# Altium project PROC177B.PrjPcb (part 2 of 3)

## Sheet PROC177B_Temp_Current_sensors_EPROM.SchDoc: TEMP_CURRENT_SENSORS_EEPROM
size 431 x 279 mm; Date: Not shown in title block; ApprovedBy: Not shown in title block; CheckedBy: Not shown in title block; Author: Not shown in title block; CompanyName: Not shown in title block; DrawnBy: Mistral; Engineer: Not shown in title block; Organization: Not shown in title block; Address1: Not shown in title block; Address2: Not shown in title block; Address3: Not shown in title block; Address4: Not shown in title block; DocumentNumber: 8; Revision: Use project parameter SCH_Rev; SheetNumber: 8; SheetTotal: 17; PageSetup: Record=PageOptions¦CenterHorizontal=True¦CenterVertical=True¦PrintScale=1.00¦XCorrection=1.00¦YCorrection=1.00¦PrintKind=0¦BorderSize=5000000¦LeftOffset=0¦BottomOffset=0¦Orientation=2¦PaperLength=1000¦PaperWidth=1000¦Scale=100¦PaperSource=15¦PrintQuality=600¦MediaType=1¦DitherType=10¦PaperKind=Letter¦PrintScaleMode=1
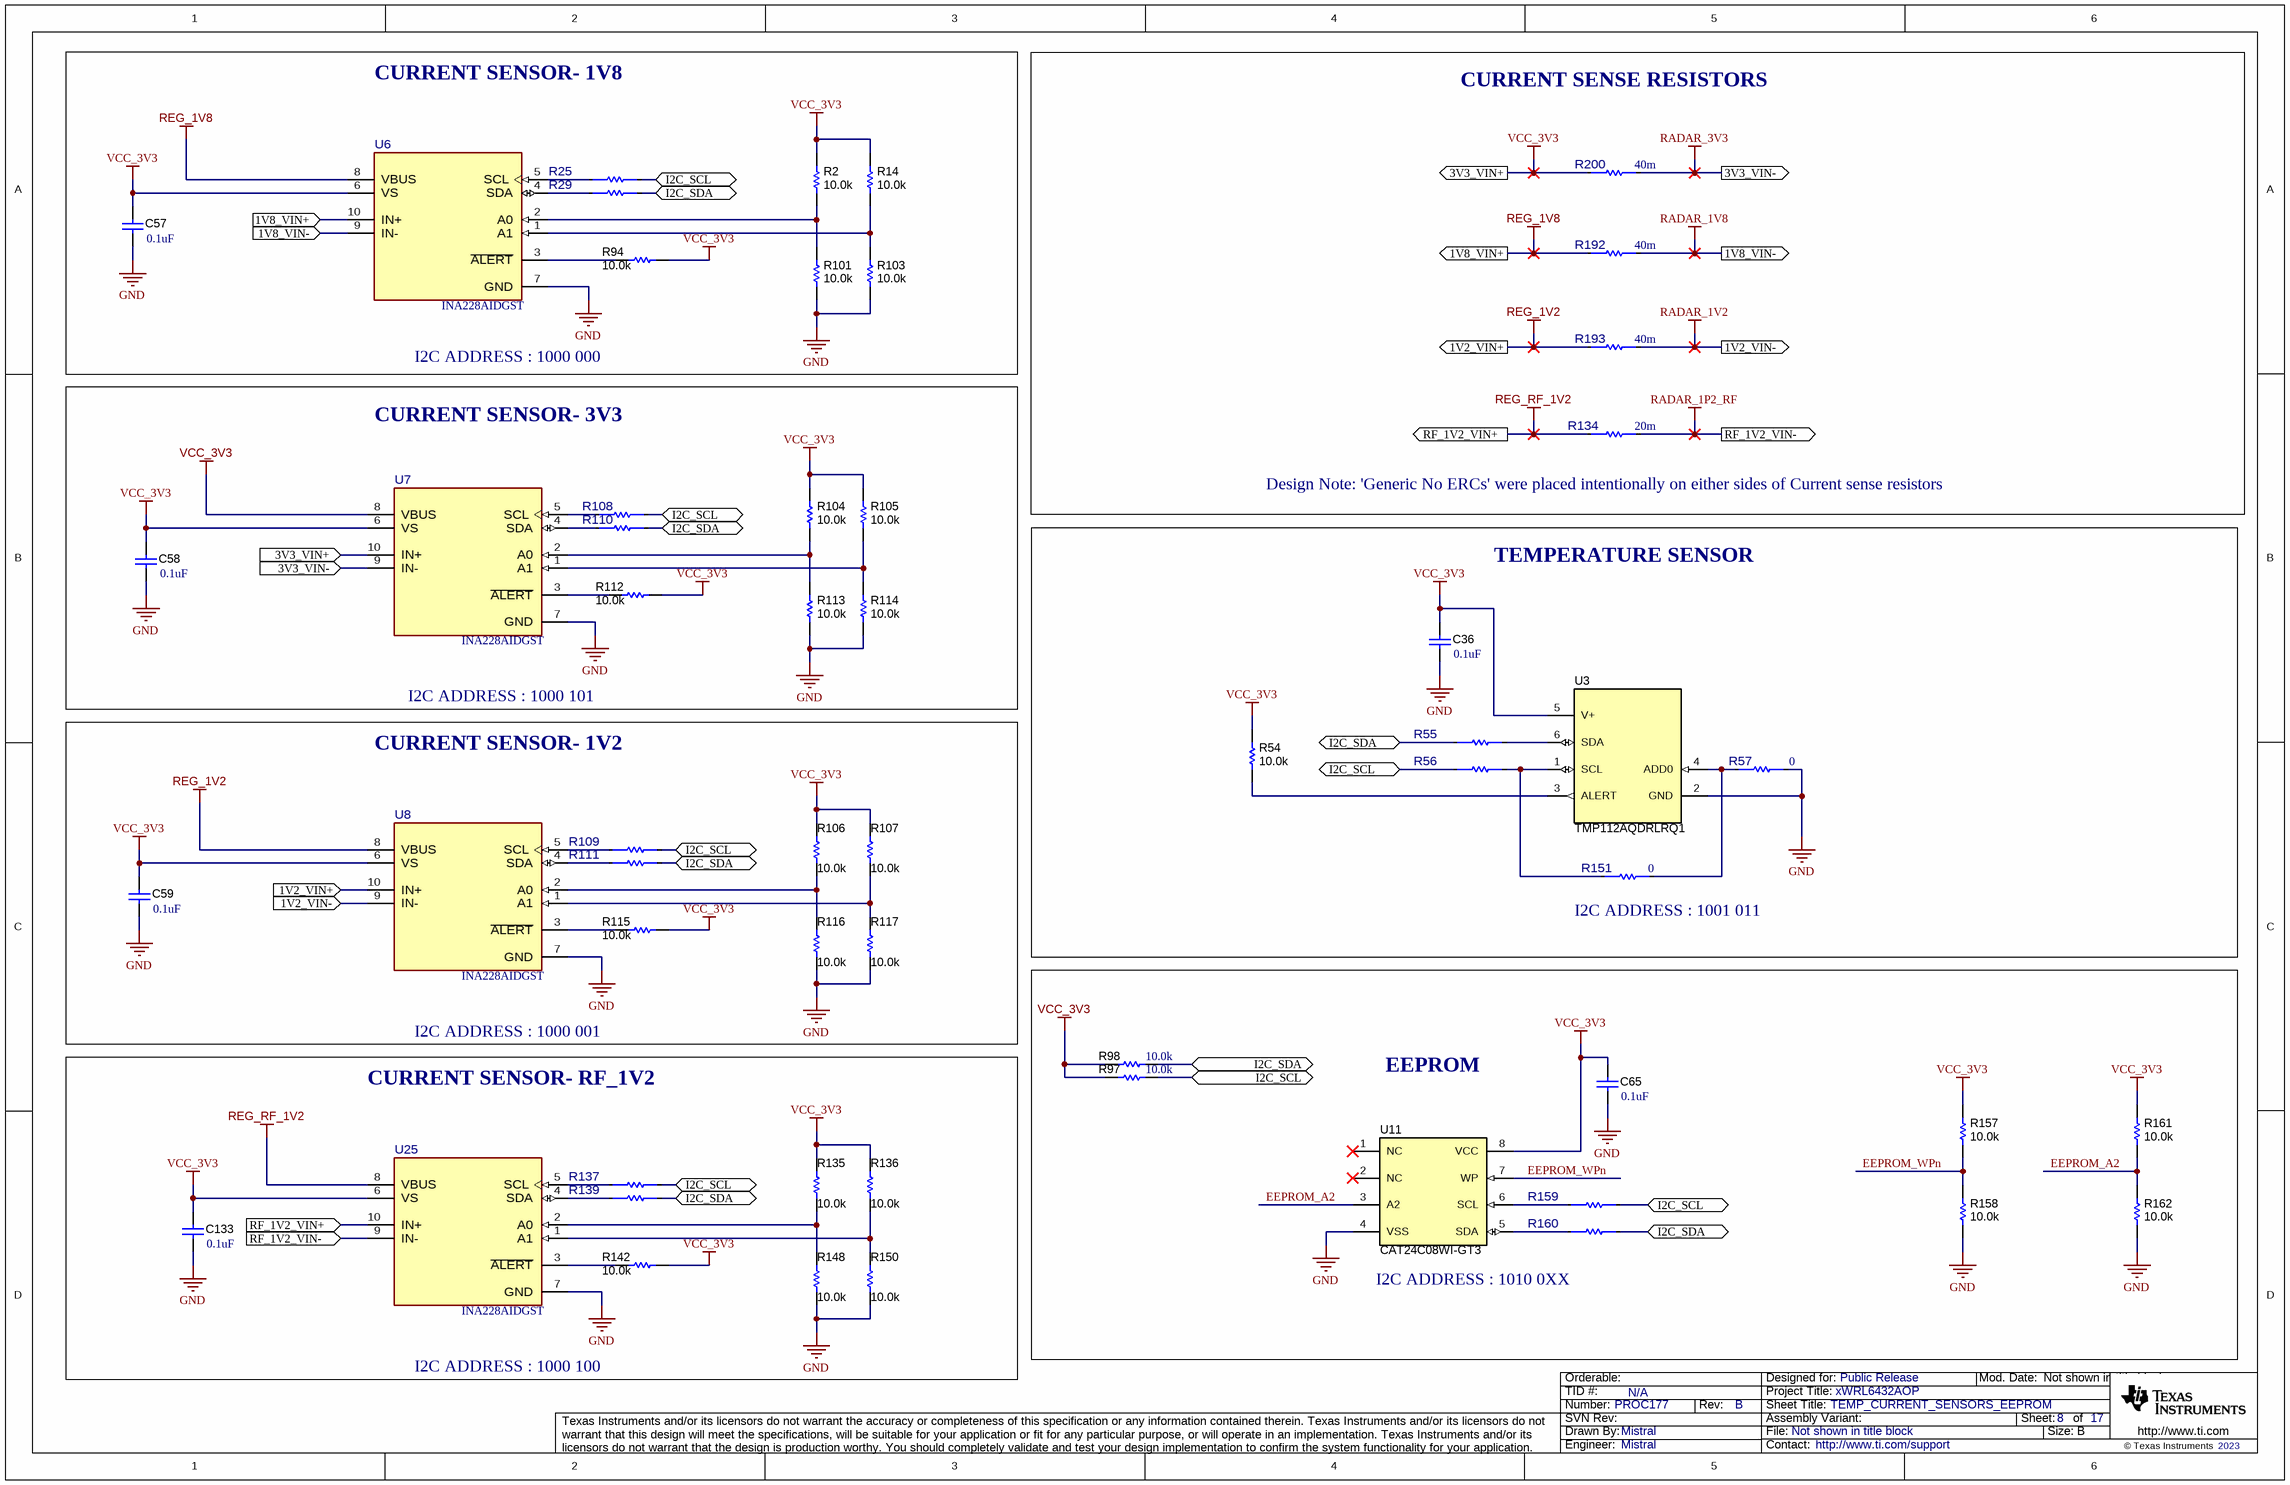
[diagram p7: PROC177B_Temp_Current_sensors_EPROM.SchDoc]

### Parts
C36  ValueDisplayed: 0.1uF  [0402]  (hidden comment: GCM155R71H104KE02D)
C57  ValueDisplayed: 0.1uF  [0402]  (hidden comment: GCM155R71H104KE02D)
C58  ValueDisplayed: 0.1uF  [0402]  (hidden comment: GCM155R71H104KE02D)
C59  ValueDisplayed: 0.1uF  [0402]  (hidden comment: GCM155R71H104KE02D)
C65  ValueDisplayed: 0.1uF  [0402]  (hidden comment: GCM155R71H104KE02D)
C133  ValueDisplayed: 0.1uF  [0402]  (hidden comment: GCM155R71H104KE02D)
R2  ValueDisplayed: 10.0k  [0402L]  (hidden comment: CRCW040210K0FKED)
R14  ValueDisplayed: 10.0k  [0402L]  (hidden comment: CRCW040210K0FKED)
R25  ERJ-2GE0R00X  [FP-ERJ-2GE0R00X_0402-MFG]  (value not drawn)
R29  ERJ-2GE0R00X  [FP-ERJ-2GE0R00X_0402-MFG]  (value not drawn)
R54  ValueDisplayed: 10.0k  [0402L]  (hidden comment: CRCW040210K0FKED)
R55  ERJ-2GE0R00X  [FP-ERJ-2GE0R00X_0402-MFG]  (value not drawn)
R56  ERJ-2GE0R00X  [FP-ERJ-2GE0R00X_0402-MFG]  (value not drawn)
R57  Res_ohm: 0  [FP-ERJ-2GE0R00X_0402-MFG]  (hidden comment: ERJ-2GE0R00X)
R94  ValueDisplayed: 10.0k  [0402L]  (hidden comment: CRCW040210K0FKED)
R97  ValueDisplayed: 10.0k  [0402L]  (hidden comment: CRCW040210K0FKED)
R98  ValueDisplayed: 10.0k  [0402L]  (hidden comment: CRCW040210K0FKED)
R101  ValueDisplayed: 10.0k  [0402L]  (hidden comment: CRCW040210K0FKED)
R103  ValueDisplayed: 10.0k  [0402L]  (hidden comment: CRCW040210K0FKED)
R104  ValueDisplayed: 10.0k  [0402L]  (hidden comment: CRCW040210K0FKED)
R105  ValueDisplayed: 10.0k  [0402L]  (hidden comment: CRCW040210K0FKED)
R106  ValueDisplayed: 10.0k  [0402L]  (hidden comment: CRCW040210K0FKED)
R107  ValueDisplayed: 10.0k  [0402L]  (hidden comment: CRCW040210K0FKED)
R108  ERJ-2GE0R00X  [FP-ERJ-2GE0R00X_0402-MFG]  (value not drawn)
R109  ERJ-2GE0R00X  [FP-ERJ-2GE0R00X_0402-MFG]  (value not drawn)
R110  ERJ-2GE0R00X  [FP-ERJ-2GE0R00X_0402-MFG]  (value not drawn)
R111  ERJ-2GE0R00X  [FP-ERJ-2GE0R00X_0402-MFG]  (value not drawn)
R112  ValueDisplayed: 10.0k  [0402L]  (hidden comment: CRCW040210K0FKED)
R113  ValueDisplayed: 10.0k  [0402L]  (hidden comment: CRCW040210K0FKED)
R114  ValueDisplayed: 10.0k  [0402L]  (hidden comment: CRCW040210K0FKED)
R115  ValueDisplayed: 10.0k  [0402L]  (hidden comment: CRCW040210K0FKED)
R116  ValueDisplayed: 10.0k  [0402L]  (hidden comment: CRCW040210K0FKED)
R117  ValueDisplayed: 10.0k  [0402L]  (hidden comment: CRCW040210K0FKED)
R134  value 20m  [FP-WSL1206R0200FEB_1206-MFG]  (hidden comment: WSL1206R0200FEB)
R135  ValueDisplayed: 10.0k  [0402L]  (hidden comment: CRCW040210K0FKED)
R136  ValueDisplayed: 10.0k  [0402L]  (hidden comment: CRCW040210K0FKED)
R137  ERJ-2GE0R00X  [FP-ERJ-2GE0R00X_0402-MFG]  (value not drawn)
R139  ERJ-2GE0R00X  [FP-ERJ-2GE0R00X_0402-MFG]  (value not drawn)
R142  ValueDisplayed: 10.0k  [0402L]  (hidden comment: CRCW040210K0FKED)
R148  ValueDisplayed: 10.0k  [0402L]  (hidden comment: CRCW040210K0FKED)
R150  ValueDisplayed: 10.0k  [0402L]  (hidden comment: CRCW040210K0FKED)
R151  Res_ohm: 0  [FP-ERJ-2GE0R00X_0402-MFG]  (hidden comment: ERJ-2GE0R00X)
R157  ValueDisplayed: 10.0k  [0402L]  (hidden comment: CRCW040210K0FKED)
R158  ValueDisplayed: 10.0k  [0402L]  (hidden comment: CRCW040210K0FKED)
R159  ERJ-2GE0R00X  [FP-ERJ-2GE0R00X_0402-MFG]  (value not drawn)
R160  ERJ-2GE0R00X  [FP-ERJ-2GE0R00X_0402-MFG]  (value not drawn)
R161  ValueDisplayed: 10.0k  [0402L]  (hidden comment: CRCW040210K0FKED)
R162  ValueDisplayed: 10.0k  [0402L]  (hidden comment: CRCW040210K0FKED)
R192  value 40m  [FP-WSL1206R0400FEB_1206-MFG]  (hidden comment: WSL1206R0400FEB)
R193  value 40m  [FP-WSL1206R0400FEB_1206-MFG]  (hidden comment: WSL1206R0400FEB)
R200  value 40m  [FP-WSL1206R0400FEB_1206-MFG]  (hidden comment: WSL1206R0400FEB)
U3  TMP112AQDRLRQ1  [DRL0006A]
U6  INA228AIDGST  [DGS0010A-MFG]
U7  INA228AIDGST  [DGS0010A-MFG]
U8  INA228AIDGST  [DGS0010A-MFG]
U11  CAT24C08WI-GT3  [SOIC-8]
U25  INA228AIDGST  [DGS0010A-MFG]

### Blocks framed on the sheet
CURRENT SENSOR- 1V8: C57 R2 R14 R25 R29 R94 R101 R103 U6
CURRENT SENSE RESISTORS: R134 R192 R193 R200
CURRENT SENSOR- 3V3: C58 R104 R105 R108 R110 R112-R114 U7
TEMPERATURE SENSOR: C36 R54-R57 R151 U3
CURRENT SENSOR- 1V2: C59 R106 R107 R109 R111 R115-R117 U8
EEPROM: C65 R97 R98 R157-R162 U11
CURRENT SENSOR- RF_1V2: C133 R135-R137 R139 R142 R148 R150 U25

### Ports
1V2_VIN+ (in), 1V2_VIN+ (out), 1V2_VIN- (in), 1V2_VIN- (out), 1V8_VIN+ (in), 1V8_VIN+ (out), 1V8_VIN- (in), 1V8_VIN- (out), 3V3_VIN+ (in), 3V3_VIN+ (out), 3V3_VIN- (in), 3V3_VIN- (out), I2C_SCL (bidir), I2C_SDA (bidir), RF_1V2_VIN+ (in), RF_1V2_VIN+ (out), RF_1V2_VIN- (in), RF_1V2_VIN- (out)

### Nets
GND: C36.2 C57.2 C58.2 C59.2 C65.2 C133.2 R57.2 R101.1 R103.1 R113.1 R114.1 R116.1 R117.1 R148.1 R150.1 R158.1 R162.1 U3.2(GND) U6.7(GND) U7.7(GND) U8.7(GND) U11.4(VSS) U25.7(GND)
RADAR_1P2_RF: R134.2 U25.9(IN-) ; port RF_1V2_VIN-
RADAR_1V2: R193.2 U8.9(IN-) ; port 1V2_VIN-
RADAR_1V8: R192.2 U6.9(IN-) ; port 1V8_VIN-
RADAR_3V3: R200.2 U7.9(IN-) ; port 3V3_VIN-
REG_1V2: R193.1 U8.8(VBUS) U8.10(IN+) ; port 1V2_VIN+
REG_1V8: R192.1 U6.8(VBUS) U6.10(IN+) ; port 1V8_VIN+
REG_RF_1V2: R134.1 U25.8(VBUS) U25.10(IN+) ; port RF_1V2_VIN+
VCC_3V3: C36.1 C57.1 C58.1 C59.1 C65.1 C133.1 R2.2 R14.2 R54.2 R94.1 R97.2 R98.2 R104.2 R105.2 R106.2 R107.2 R112.1 R115.1 R135.2 R136.2 R142.1 R157.2 R161.2 R200.1 U3.5(V+) U6.6(VS) U7.6(VS) U7.8(VBUS) U7.10(IN+) U8.6(VS) U11.8(VCC) U25.6(VS) ; port 3V3_VIN+
EEPROM_A2: R161.1 R162.2 U11.3(A2)
EEPROM_WPn: R157.1 R158.2 U11.7(WP)
I2C_SCL: R25.2 R56.1 R97.1 R108.2 R109.2 R137.2 R159.2 ; port I2C_SCL
I2C_SDA: R29.2 R55.1 R98.1 R110.2 R111.2 R139.2 R160.2 ; port I2C_SDA
NetR2_1: R2.1 R101.2 U6.2(A0)
NetR14_1: R14.1 R103.2 U6.1(A1)
NetR25_1: R25.1 U6.5(SCL)
NetR29_1: R29.1 U6.4(SDA)
NetR54_1: R54.1 U3.3(ALERT)
NetR55_2: R55.2 U3.6(SDA)
NetR56_2: R56.2 R151.1 U3.1(SCL)
NetR57_1: R57.1 R151.2 U3.4(ADD0)
NetR94_2: R94.2 U6.3(~{ALERT})
NetR104_1: R104.1 R113.2 U7.2(A0)
NetR105_1: R105.1 R114.2 U7.1(A1)
NetR106_1: R106.1 R116.2 U8.2(A0)
NetR107_1: R107.1 R117.2 U8.1(A1)
NetR108_1: R108.1 U7.5(SCL)
NetR109_1: R109.1 U8.5(SCL)
NetR110_1: R110.1 U7.4(SDA)
NetR111_1: R111.1 U8.4(SDA)
NetR112_2: R112.2 U7.3(~{ALERT})
NetR115_2: R115.2 U8.3(~{ALERT})
NetR135_1: R135.1 R148.2 U25.2(A0)
NetR136_1: R136.1 R150.2 U25.1(A1)
NetR137_1: R137.1 U25.5(SCL)
NetR139_1: R139.1 U25.4(SDA)
NetR142_2: R142.2 U25.3(~{ALERT})
NetR159_1: R159.1 U11.6(SCL)
NetR160_1: R160.1 U11.5(SDA)

Not connected (* = marked no-connect by the designer): U11 1(NC)* 2(NC)*

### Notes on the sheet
- I2C ADDRESS : 1000 000
- (near R134) Design Note: 'Generic No ERCs' were placed intentionally on either sides of Current sense resistors
- I2C ADDRESS : 1000 101
- (near R151) I2C ADDRESS : 1001 011
- I2C ADDRESS : 1000 001
- I2C ADDRESS : 1010 0XX
- I2C ADDRESS : 1000 100

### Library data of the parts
C36 C57-C59 C65 C133 = CMP-0006356-2: CAP, CERM, 0.1 uF, 50 V, +/- 10%, X7R, AEC-Q200 Grade 1, 0402; Manufacturer: MuRata; TaMin_C: -55°C; Polarized: N; SizeAreaWB_mm2: 3; Value1: Unknown; U/M: EA; Value: 0.1uF; TaMax_C: 125°C; SizeZ_mm: 0.6; SizeX_mm: 1; SizeY_mm: 0.5; Value2: 50V; AEC Qualified: Y; Cap_F: 100nF; AEC Category: Q200
R2 R14 R54 R94 R97 R98 R101 R103-R107 R112-R117 R135 R136 R142 R148 R150 R157 R158 R161 R162 = CMP-0025958-3: RES, 10.0 k, 1%, 0.063 W, AEC-Q200 Grade 0, 0402; Manufacturer: Vishay-Dale; Power_W: 63mW; TempCo: 100 ppm/C; Value_Code: 10k0; Value: 10.0k; EIA_Code: E96; Res_ohm: 10k; SizeX_mm: 1; SizeY_mm: 0.5; SizeZ_mm: 0.6; Value2: 0.063W; AEC Qualified: Y; VDC_V: 50V; AEC Category: Q200; AEC Grade: 0
R25 R29 R55-R57 R108-R111 R137 R139 R151 R159 R160 = CMP-0002710-1: 0 Ohms Jumper Chip Resistor 0402 (1005 Metric) Automotive AEC-Q200 Thick Film; Manufacturer: Panasonic; Value: 0; SizeZ_mm: 0.4mm; AEC Qualified: Yes; AEC Grade: Grade 0; Power: 100mW
R134 = CMP-0098430-1: Res Metal Strip 1206 0.02 Ohm 1% 1/4W ±75ppm/°C Molded SMD SMD T/R; Manufacturer: Vishay Dale; AEC Grade: Grade 0; AEC Qualified: Yes; Power_W: 250mW; SizeZ_mm: 0.889mm; Category 5C6A91606D4187Ad: Resistors; Category 7542B8484461Ae85: Passive Components; Category Cd01000Bfc2916C6: Single Components
R192 R193 R200 = CMP-0098431-1: 40 mOhms ±1% 0.25W, 1/4W Chip Resistor Automotive AEC-Q200, Current Sense, Moisture Resistant, Pulse Withstanding Metal Element; Manufacturer: Vishay; AEC Grade: Grade 0; AEC Qualified: Yes; Power_W: 250mW; SizeZ_mm: 0.889mm; TempCo: 75ppm/°C
U3 = CMP-0067398-2: Automotive Grade, 1.4V-Capable +/-0.5degC Temperature Sensor with Alert Function and I2C/SMBus, DRL0006A (SOT-OTHER-6); Manufacturer: Texas Instruments; SizeZ_mm: 0.6; SizeX_mm: 1.6; SizeArea_mm2: 2.56; CompType: IC; U/M: EA; SizeAreaWB_mm2: 6.76
U6-U8 U25 = CMP-0098432-1: Current Sense Amplifier 1 Circuit 10-VSSOP; Manufacturer: Texas Instruments; SizeZ_mm: 1.1mm; AEC Qualified: No; Input Bias Current: 0.01uA; Input Offset Voltage: 1mV; Max Supply Voltage: 5.5V; Min Supply Voltage: 2.7V; Nominal Supply Current: 640uA; Number Of Channels: 1; Standoff Height: 0.05mm; TaMax_C: +125°C; TaMin_C: -40°C; TJmax_C: +150°C
U11 = CMP-0005309-2: IC, EEPROM, 8KBIT, 400KHZ, 8SOIC; Manufacturer: ON Semiconductor; SizeAreaWB_mm2: 55.131; SizeZ_mm: 1.75; SizeX_mm: 5.99; SizeY_mm: 4.9; SizeArea_mm2: 29.351

## Sheet PROC177B_LVDS_Driver.SchDoc: LVDS_DRIVER
size 431 x 279 mm; Date: Not shown in title block; ApprovedBy: Not shown in title block; CheckedBy: Not shown in title block; Author: Not shown in title block; CompanyName: Not shown in title block; DrawnBy: Mistral; Engineer: Not shown in title block; Organization: Not shown in title block; Address1: Not shown in title block; Address2: Not shown in title block; Address3: Not shown in title block; Address4: Not shown in title block; DocumentNumber: 10; Revision: Use project parameter SCH_Rev; SheetNumber: 9; SheetTotal: 17; PageSetup: Record=PageOptions¦CenterHorizontal=True¦CenterVertical=True¦PrintScale=1.00¦XCorrection=1.00¦YCorrection=1.00¦PrintKind=0¦BorderSize=5000000¦LeftOffset=0¦BottomOffset=0¦Orientation=2¦PaperLength=1000¦PaperWidth=1000¦Scale=100¦PaperSource=15¦PrintQuality=600¦MediaType=1¦DitherType=10¦PaperKind=Letter¦PrintScaleMode=1
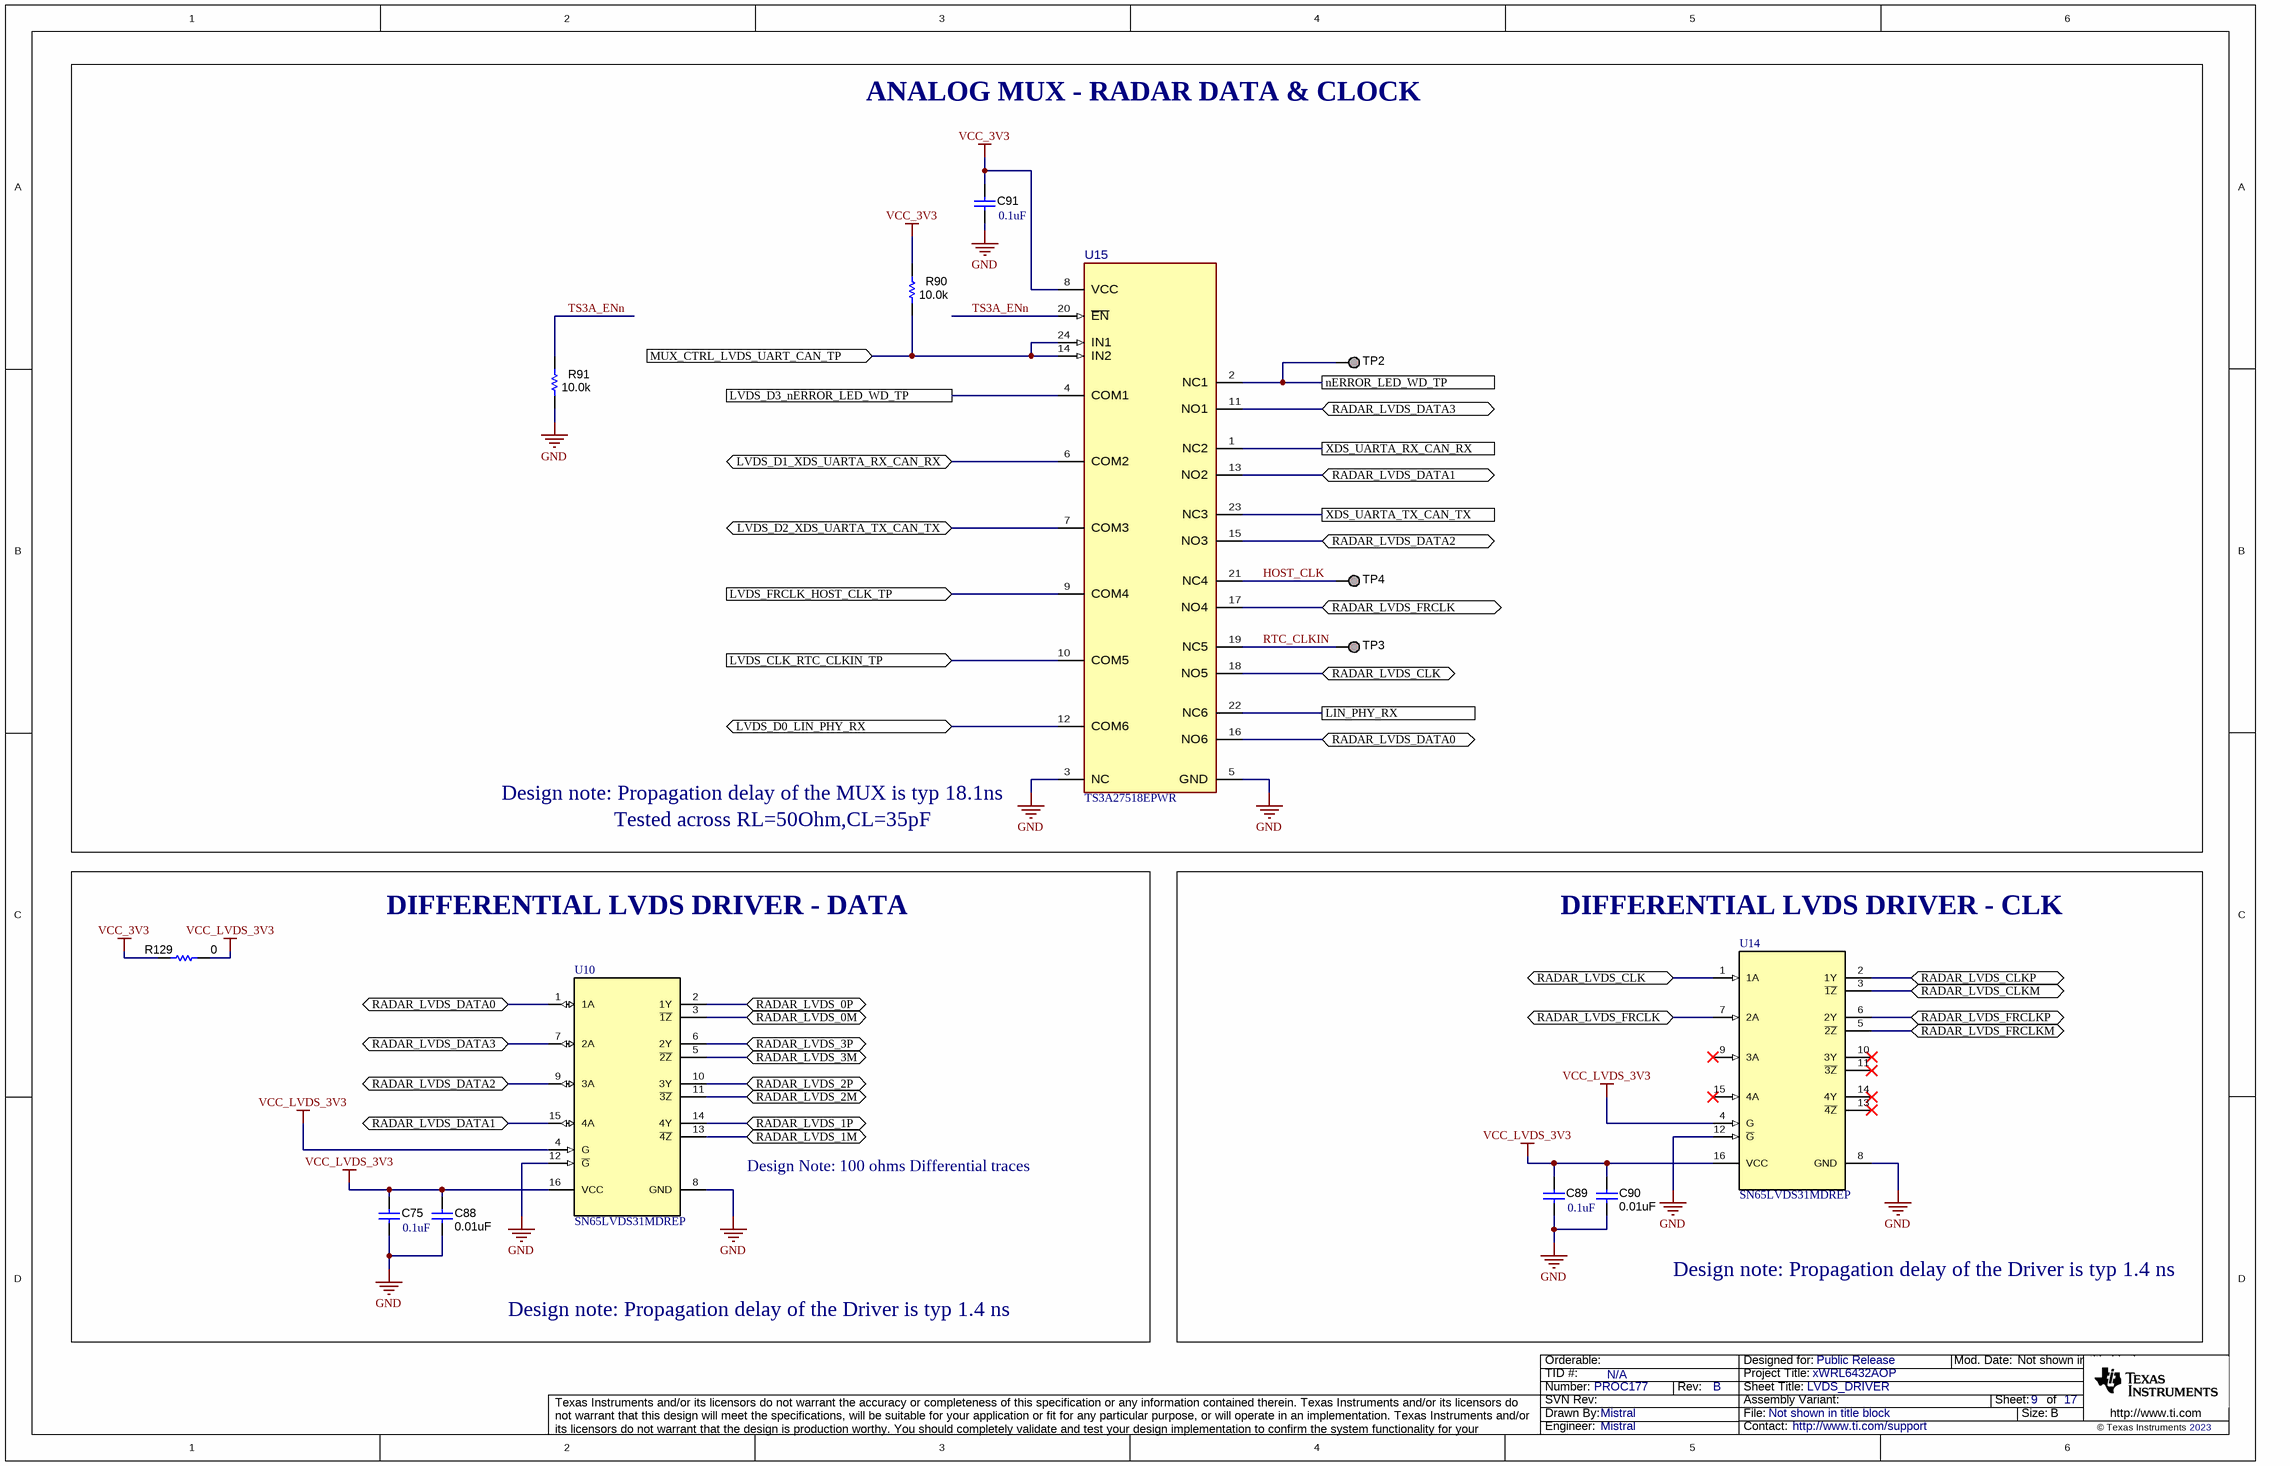
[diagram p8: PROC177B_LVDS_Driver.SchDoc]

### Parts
C75  ValueDisplayed: 0.1uF  [0402]  (hidden comment: GCM155R71H104KE02D)
C88  ValueDisplayed: 0.01uF  [0402L]  (hidden comment: GCM155R71E103KA37D)
C89  ValueDisplayed: 0.1uF  [0402]  (hidden comment: GCM155R71H104KE02D)
C90  ValueDisplayed: 0.01uF  [0402L]  (hidden comment: GCM155R71E103KA37D)
C91  ValueDisplayed: 0.1uF  [0402]  (hidden comment: GCM155R71H104KE02D)
R90  ValueDisplayed: 10.0k  [0402L]  (hidden comment: CRCW040210K0FKED)
R91  ValueDisplayed: 10.0k  [0402L]  (hidden comment: CRCW040210K0FKED)
R129  ValueDisplayed: 0  [0603]  (hidden comment: MCT06030Z0000ZP500)
TP2  TESTPOINT  [TP_25MIL-SMT]  (value not drawn)  (no BOM)
TP3  TESTPOINT  [TP_25MIL-SMT]  (value not drawn)  (no BOM)
TP4  TESTPOINT  [TP_25MIL-SMT]  (value not drawn)  (no BOM)
U10  SN65LVDS31MDREP  [D0016A_N]
U14  SN65LVDS31MDREP  [D0016A_N]
U15  TS3A27518EPWR  [PW0024A-MFG]

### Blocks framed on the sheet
ANALOG MUX - RADAR DATA & CLOCK: C91 R90 R91 TP2-TP4 U15
DIFFERENTIAL LVDS DRIVER - DATA: C75 C88 R129 U10
DIFFERENTIAL LVDS DRIVER - CLK: C89 C90 U14

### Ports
LIN_PHY_RX, LVDS_CLK_RTC_CLKIN_TP (in), LVDS_D0_LIN_PHY_RX (bidir), LVDS_D1_XDS_UARTA_RX_CAN_RX (bidir), LVDS_D2_XDS_UARTA_TX_CAN_TX (bidir), LVDS_D3_nERROR_LED_WD_TP, LVDS_FRCLK_HOST_CLK_TP (in), MUX_CTRL_LVDS_UART_CAN_TP (in), nERROR_LED_WD_TP, RADAR_LVDS_0M (bidir), RADAR_LVDS_0P (bidir), RADAR_LVDS_1M (bidir), RADAR_LVDS_1P (bidir), RADAR_LVDS_2M (bidir), RADAR_LVDS_2P (bidir), RADAR_LVDS_3M (bidir), RADAR_LVDS_3P (bidir), RADAR_LVDS_CLK (bidir), RADAR_LVDS_CLKM (bidir), RADAR_LVDS_CLKP (bidir), RADAR_LVDS_DATA0 (bidir), RADAR_LVDS_DATA1 (bidir), RADAR_LVDS_DATA2 (bidir), RADAR_LVDS_DATA3 (bidir), RADAR_LVDS_FRCLK (bidir), RADAR_LVDS_FRCLKM (bidir), RADAR_LVDS_FRCLKP (bidir), XDS_UARTA_RX_CAN_RX, XDS_UARTA_TX_CAN_TX

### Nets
GND: C75.2 C88.2 C89.2 C90.2 C91.2 R91.2 U10.8(GND) U10.12(~{G}) U14.8(GND) U14.12(~{G}) U15.3(NC) U15.5(GND)
VCC_3V3: C91.1 R90.1 R129.1 U15.8(VCC)
VCC_LVDS_3V3: C75.1 C88.1 C89.1 C90.1 R129.2 U10.4(G) U10.16(VCC) U14.4(G) U14.16(VCC)
HOST_CLK: TP4.1 U15.21(NC4)
LIN_PHY_RX: U15.22(NC6) ; port LIN_PHY_RX
LVDS_CLK_RTC_CLKIN_TP: U15.10(COM5) ; port LVDS_CLK_RTC_CLKIN_TP
LVDS_D0_LIN_PHY_RX: U15.12(COM6) ; port LVDS_D0_LIN_PHY_RX
LVDS_D1_XDS_UARTA_RX_CAN_RX: U15.6(COM2) ; port LVDS_D1_XDS_UARTA_RX_CAN_RX
LVDS_D2_XDS_UARTA_TX_CAN_TX: U15.7(COM3) ; port LVDS_D2_XDS_UARTA_TX_CAN_TX
LVDS_D3_nERROR_LED_WD_TP: U15.4(COM1) ; port LVDS_D3_nERROR_LED_WD_TP
LVDS_FRCLK_HOST_CLK_TP: U15.9(COM4) ; port LVDS_FRCLK_HOST_CLK_TP
MUX_CTRL_LVDS_UART_CAN_TP: R90.2 U15.14(IN2) U15.24(IN1) ; port MUX_CTRL_LVDS_UART_CAN_TP
nERROR_LED_WD_TP: TP2.1 U15.2(NC1) ; port nERROR_LED_WD_TP
RADAR_LVDS_0M: U10.3(~{1Z}) ; port RADAR_LVDS_0M
RADAR_LVDS_0P: U10.2(1Y) ; port RADAR_LVDS_0P
RADAR_LVDS_1M: U10.13(~{4Z}) ; port RADAR_LVDS_1M
RADAR_LVDS_1P: U10.14(4Y) ; port RADAR_LVDS_1P
RADAR_LVDS_2M: U10.11(~{3Z}) ; port RADAR_LVDS_2M
RADAR_LVDS_2P: U10.10(3Y) ; port RADAR_LVDS_2P
RADAR_LVDS_3M: U10.5(~{2Z}) ; port RADAR_LVDS_3M
RADAR_LVDS_3P: U10.6(2Y) ; port RADAR_LVDS_3P
RADAR_LVDS_CLK: U14.1(1A) U15.18(NO5) ; port RADAR_LVDS_CLK
RADAR_LVDS_CLKM: U14.3(~{1Z}) ; port RADAR_LVDS_CLKM
RADAR_LVDS_CLKP: U14.2(1Y) ; port RADAR_LVDS_CLKP
RADAR_LVDS_DATA0: U10.1(1A) U15.16(NO6) ; port RADAR_LVDS_DATA0
RADAR_LVDS_DATA1: U10.15(4A) U15.13(NO2) ; port RADAR_LVDS_DATA1
RADAR_LVDS_DATA2: U10.9(3A) U15.15(NO3) ; port RADAR_LVDS_DATA2
RADAR_LVDS_DATA3: U10.7(2A) U15.11(NO1) ; port RADAR_LVDS_DATA3
RADAR_LVDS_FRCLK: U14.7(2A) U15.17(NO4) ; port RADAR_LVDS_FRCLK
RADAR_LVDS_FRCLKM: U14.5(~{2Z}) ; port RADAR_LVDS_FRCLKM
RADAR_LVDS_FRCLKP: U14.6(2Y) ; port RADAR_LVDS_FRCLKP
RTC_CLKIN: TP3.1 U15.19(NC5)
TS3A_ENn: R91.1 U15.20(~{EN})
XDS_UARTA_RX_CAN_RX: U15.1(NC2) ; port XDS_UARTA_RX_CAN_RX
XDS_UARTA_TX_CAN_TX: U15.23(NC3) ; port XDS_UARTA_TX_CAN_TX

Not connected (* = marked no-connect by the designer): U14 9(3A)* 10(3Y)* 11(~{3Z})* 13(~{4Z})* 14(4Y)* 15(4A)*

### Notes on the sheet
- (near U15) Design note: Propagation delay of the MUX is typ 18.1ns
- Tested across RL=50Ohm,CL=35pF
- Design Note: 100 ohms Differential traces
- Design note: Propagation delay of the Driver is typ 1.4 ns

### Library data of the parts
C75 C89 C91 = CMP-0006356-2: as C36 on sheet PROC177B_Temp_Current_sensors_EPROM
C88 C90 = CMP-0006352-2: CAP, CERM, 0.01 uF, 25 V, +/- 10%, X7R, 0402; Manufacturer: MuRata; TaMin_C: -55°C; Polarized: N; SizeAreaWB_mm2: 3; Value1: Unknown; U/M: EA; Value: 0.01uF; TaMax_C: 125°C; SizeZ_mm: 0.6; SizeX_mm: 1; SizeY_mm: 0.5; Cap_Case: 0402; Value2: 25V; CompType: Capacitor; Cap_F: 10nF; AEC Category: Q200
R90 R91 = CMP-0025958-3: as R2 on sheet PROC177B_Temp_Current_sensors_EPROM
R129 = CMP-0025884-3: RES, 0, 5%, 0.125 W, 0603; Manufacturer: Vishay/Beyschlag; Power_W: 125mW; TempCo: ppm/C; Value_Code: 0000; U/M: EA; Value: 0; EIA_Code: E24; SizeX_mm: 1.6; SizeY_mm: 0.8; SizeZ_mm: 1; Value2: 0.125W; SizeArea_mm2: 1.28; CompType: Resistor; AEC Qualified: N; AEC Category: Q200; INSTALATION: DNP
TP2-TP4 = CMP-0078143-3: TEST POINT.  No entry in BOM.
U10 U14 = CMP-0029468-1: 400 Mbps Enhanced Product Quad LVDS Transmitter with LVTTL Input and Output, 4 Tx and 0 Rx, -55 to +125 degC, 16-pin SOIC (D), Green (RoHS & no Sb/Br); Manufacturer: Texas Instruments; ESD HBM(kV): 8; Signaling Rate(Mbps): 400; ICC(Max)(mA): 35; No. of Tx: 4; SubFamily: LVDS PHY (<800Mbps)
U15 = CMP-0092155-1: 3.3-V, 2:1 (SPDT), 6-channel analog multiplexer with 1.8-V compatible control inputs 24-TSSOP -40 to 85; Manufacturer: Texas Instruments; Max Supply Voltage: 3.6V; -3Db Bandwith: 240MHz; Standoff Height: 0.05mm; Category 9E37533Dafe045F0: Logic, Standard; SizeZ_mm: 1.2mm; On State Resistance: 4.4Ω; Category Aef863F29A99753F: Switches; AEC Qualified: No; Category 9E07530Daf1645C0: Semiconductors and Actives; Min Supply Voltage: 1.65V; Nominal Supply Current: 0.01-0.04uA; PositionCount: 6

## Sheet PROC177B_Analog_Mux_SOP_Ctrl.SchDoc: ANALOG_MUX_SOP_CTRL
size 431 x 279 mm; Date: Not shown in title block; ApprovedBy: Not shown in title block; CheckedBy: Not shown in title block; Author: Not shown in title block; CompanyName: Not shown in title block; DrawnBy: Mistral; Engineer: Not shown in title block; Organization: Not shown in title block; Address1: Not shown in title block; Address2: Not shown in title block; Address3: Not shown in title block; Address4: Not shown in title block; DocumentNumber: 9; Revision: Use project parameter SCH_Rev; SheetNumber: 10; SheetTotal: 17; PageSetup: Record=PageOptions¦CenterHorizontal=True¦CenterVertical=True¦PrintScale=1.00¦XCorrection=1.00¦YCorrection=1.00¦PrintKind=0¦BorderSize=5000000¦LeftOffset=0¦BottomOffset=0¦Orientation=2¦PaperLength=1000¦PaperWidth=1000¦Scale=100¦PaperSource=15¦PrintQuality=600¦MediaType=1¦DitherType=10¦PaperKind=Letter¦PrintScaleMode=1
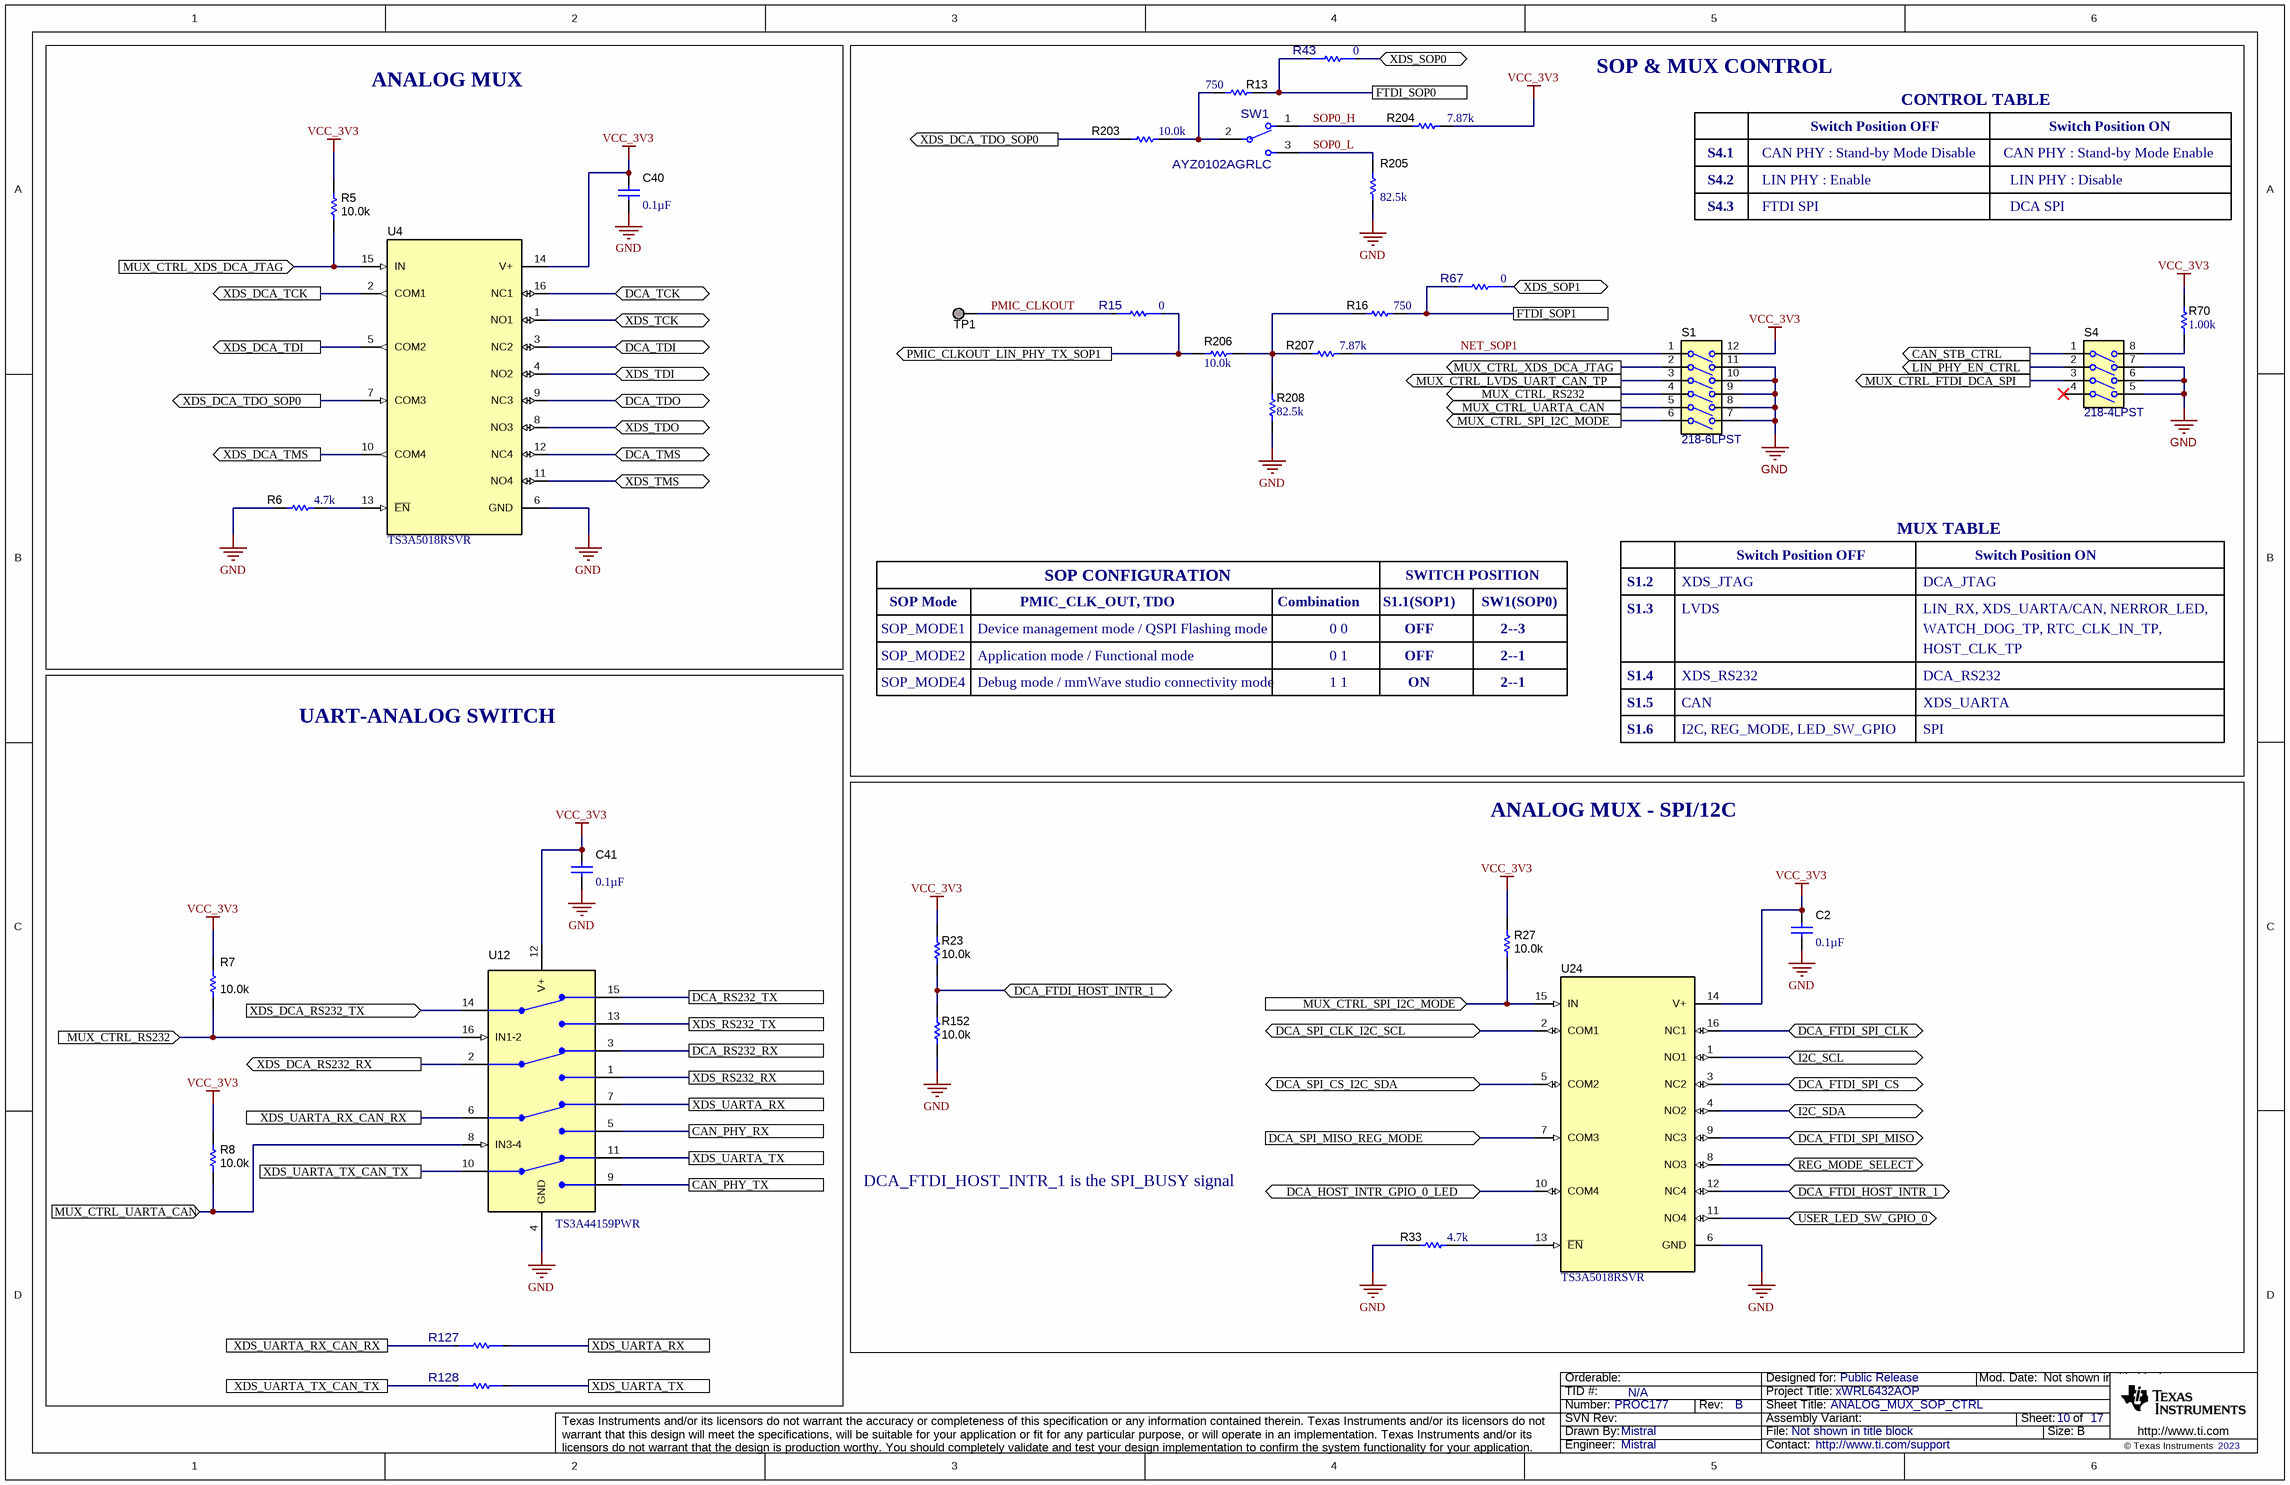
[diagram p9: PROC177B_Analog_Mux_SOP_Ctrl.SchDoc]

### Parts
C2  ValueDisplayed: 0.1µF  [0402]  (hidden comment: C0402C104K8RACTU)
C40  ValueDisplayed: 0.1µF  [0402]  (hidden comment: C0402C104K8RACTU)
C41  ValueDisplayed: 0.1µF  [0402]  (hidden comment: C0402C104K8RACTU)
R5  ValueDisplayed: 10.0k  [0402L]  (hidden comment: CRCW040210K0FKED)
R6  ValueDisplayed: 4.7k  [0402]  (hidden comment: CRCW04024K70JNED)
R7  ValueDisplayed: 10.0k  [0402L]  (hidden comment: CRCW040210K0FKED)
R8  ValueDisplayed: 10.0k  [0402L]  (hidden comment: CRCW040210K0FKED)
R13  ValueDisplayed: 750  [0402L]  (hidden comment: CRCW0402750RFKED)
R15  value 0  [FP-ERJ-2GE0R00X_0402-MFG]  (hidden comment: ERJ-2GE0R00X)
R16  ValueDisplayed: 750  [0402L]  (hidden comment: CRCW0402750RFKED)
R23  ValueDisplayed: 10.0k  [0402L]  (hidden comment: CRCW040210K0FKED)
R27  ValueDisplayed: 10.0k  [0402L]  (hidden comment: CRCW040210K0FKED)
R33  ValueDisplayed: 4.7k  [0402]  (hidden comment: CRCW04024K70JNED)
R43  value 0  [FP-ERJ-2GE0R00X_0402-MFG]  (hidden comment: ERJ-2GE0R00X)
R67  value 0  [FP-ERJ-2GE0R00X_0402-MFG]  (hidden comment: ERJ-2GE0R00X)
R70  ValueDisplayed: 1.00k  [0402]  (hidden comment: CRCW04021K00FKED)
R127  ERJ-2GE0R00X  [FP-ERJ-2GE0R00X_0402-MFG]  (value not drawn)
R128  ERJ-2GE0R00X  [FP-ERJ-2GE0R00X_0402-MFG]  (value not drawn)
R152  ValueDisplayed: 10.0k  [0402L]  (hidden comment: CRCW040210K0FKED)
R203  ValueDisplayed: 10.0k  [0402L]  (hidden comment: CRCW040210K0FKED)
R204  ValueDisplayed: 7.87k  [0402L]  (hidden comment: CRCW04027K87FKED)
R205  ValueDisplayed: 82.5k  [0402L]  (hidden comment: CRCW040282K5FKED)
R206  ValueDisplayed: 10.0k  [0402L]  (hidden comment: CRCW040210K0FKED)
R207  ValueDisplayed: 7.87k  [0402L]  (hidden comment: CRCW04027K87FKED)
R208  ValueDisplayed: 82.5k  [0402L]  (hidden comment: CRCW040282K5FKED)
S1  218-6LPST  [SW_218-6LPST]
S4  218-4LPST  [SW_218-4LPST]
SW1  AYZ0102AGRLC  [FP-AYZ0102AGRLC_SMT_SW_7MM2_5MM3-MFG]
TP1  TESTPOINT  [TP_25MIL-SMT]  (value not drawn)  (no BOM)
U4  TS3A5018RSVR  [RSV0016A]
U12  TS3A44159PWR  [PW0016A_N]
U24  TS3A5018RSVR  [RSV0016A]

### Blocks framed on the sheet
ANALOG MUX: C40 R5 R6 U4
SOP & MUX CONTROL: R13 R15 R16 R43 R67 R70 R203-R208 S1 S4 SW1 TP1
UART-ANALOG SWITCH: C41 R7 R8 R127 R128 U12
ANALOG MUX - SPI/12C: C2 R23 R27 R33 R152 U24

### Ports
CAN_PHY_RX, CAN_PHY_TX, CAN_STB_CTRL (out), DCA_FTDI_HOST_INTR_1 (bidir), DCA_FTDI_SPI_CLK (bidir), DCA_FTDI_SPI_CS (bidir), DCA_FTDI_SPI_MISO (bidir), DCA_HOST_INTR_GPIO_0_LED (bidir), DCA_RS232_RX, DCA_RS232_TX, DCA_SPI_CLK_I2C_SCL (bidir), DCA_SPI_CS_I2C_SDA (bidir), DCA_SPI_MISO_REG_MODE (in), DCA_TCK (bidir), DCA_TDI (bidir), DCA_TDO (bidir), DCA_TMS (bidir), FTDI_SOP0, FTDI_SOP1, I2C_SCL (bidir), I2C_SDA (bidir), LIN_PHY_EN_CTRL (out), MUX_CTRL_FTDI_DCA_SPI (out), MUX_CTRL_LVDS_UART_CAN_TP (out), MUX_CTRL_RS232 (in), MUX_CTRL_RS232 (out), MUX_CTRL_SPI_I2C_MODE (in), MUX_CTRL_SPI_I2C_MODE (out), MUX_CTRL_UARTA_CAN (in), MUX_CTRL_UARTA_CAN (out), MUX_CTRL_XDS_DCA_JTAG (in), MUX_CTRL_XDS_DCA_JTAG (out), PMIC_CLKOUT_LIN_PHY_TX_SOP1 (out), REG_MODE_SELECT (bidir), USER_LED_SW_GPIO_0 (bidir), XDS_DCA_RS232_RX (out), XDS_DCA_RS232_TX (in), XDS_DCA_TCK (out), XDS_DCA_TDI (out), XDS_DCA_TDO_SOP0 (out), XDS_DCA_TMS (out), XDS_RS232_RX, XDS_RS232_TX, XDS_SOP0 (bidir), XDS_SOP1 (bidir), XDS_TCK (bidir), XDS_TDI (bidir), XDS_TDO (bidir), XDS_TMS (bidir), XDS_UARTA_RX, XDS_UARTA_RX_CAN_RX, XDS_UARTA_TX, XDS_UARTA_TX_CAN_TX

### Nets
GND: C2.2 C40.2 C41.2 R6.1 R33.1 R152.2 R205.1 R208.1 S1.7(6A) S1.8(5A) S1.9(4A) S1.10(3A) S1.11(2A) S4.5(B4) S4.6(B3) S4.7(B2) U4.6(GND) U12.4(GND) U24.6(GND)
VCC_3V3: C2.1 C40.1 C41.1 R5.2 R7.2 R8.2 R23.1 R27.2 R70.2 R204.2 S1.12(1A) U4.14(V+) U12.12(V+) U24.14(V+)
CAN_PHY_RX: U12.5(NO3) ; port CAN_PHY_RX
CAN_PHY_TX: U12.9(NO4) ; port CAN_PHY_TX
CAN_STB_CTRL: S4.1(A1) ; port CAN_STB_CTRL
DCA_FTDI_HOST_INTR_1: R23.2 R152.1 U24.12(NC4) ; port DCA_FTDI_HOST_INTR_1
DCA_FTDI_SPI_CLK: U24.16(NC1) ; port DCA_FTDI_SPI_CLK
DCA_FTDI_SPI_CS: U24.3(NC2) ; port DCA_FTDI_SPI_CS
DCA_FTDI_SPI_MISO: U24.9(NC3) ; port DCA_FTDI_SPI_MISO
DCA_HOST_INTR_GPIO_0_LED: U24.10(COM4) ; port DCA_HOST_INTR_GPIO_0_LED
DCA_RS232_RX: U12.3(NC2) ; port DCA_RS232_RX
DCA_RS232_TX: U12.15(NC1) ; port DCA_RS232_TX
DCA_SPI_CLK_I2C_SCL: U24.2(COM1) ; port DCA_SPI_CLK_I2C_SCL
DCA_SPI_CS_I2C_SDA: U24.5(COM2) ; port DCA_SPI_CS_I2C_SDA
DCA_SPI_MISO_REG_MODE: U24.7(COM3) ; port DCA_SPI_MISO_REG_MODE
DCA_TCK: U4.16(NC1) ; port DCA_TCK
DCA_TDI: U4.3(NC2) ; port DCA_TDI
DCA_TDO: U4.9(NC3) ; port DCA_TDO
DCA_TMS: U4.12(NC4) ; port DCA_TMS
FTDI_SOP0: R13.1 R43.2 ; port FTDI_SOP0
FTDI_SOP1: R16.1 R67.2 ; port FTDI_SOP1
I2C_SCL: U24.1(NO1) ; port I2C_SCL
I2C_SDA: U24.4(NO2) ; port I2C_SDA
LIN_PHY_EN_CTRL: S4.2(A2) ; port LIN_PHY_EN_CTRL
MUX_CTRL_FTDI_DCA_SPI: S4.3(A3) ; port MUX_CTRL_FTDI_DCA_SPI
MUX_CTRL_LVDS_UART_CAN_TP: S1.3 ; port MUX_CTRL_LVDS_UART_CAN_TP
MUX_CTRL_RS232: R7.1 S1.4 U12.16(IN1-2) ; port MUX_CTRL_RS232
MUX_CTRL_SPI_I2C_MODE: R27.1 S1.6 U24.15(IN) ; port MUX_CTRL_SPI_I2C_MODE
MUX_CTRL_UARTA_CAN: R8.1 S1.5 U12.8(IN3-4) ; port MUX_CTRL_UARTA_CAN
MUX_CTRL_XDS_DCA_JTAG: R5.1 S1.2 U4.15(IN) ; port MUX_CTRL_XDS_DCA_JTAG
NET_SOP1: R207.2 S1.1
PMIC_CLKOUT: R15.2 TP1.1
PMIC_CLKOUT_LIN_PHY_TX_SOP1: R15.1 R206.1 ; port PMIC_CLKOUT_LIN_PHY_TX_SOP1
REG_MODE_SELECT: U24.8(NO3) ; port REG_MODE_SELECT
SOP0_H: R204.1 SW1.1
SOP0_L: R205.2 SW1.3
USER_LED_SW_GPIO_0: U24.11(NO4) ; port USER_LED_SW_GPIO_0
XDS_DCA_RS232_RX: U12.2(COM2) ; port XDS_DCA_RS232_RX
XDS_DCA_RS232_TX: U12.14(COM1) ; port XDS_DCA_RS232_TX
XDS_DCA_TCK: U4.2(COM1) ; port XDS_DCA_TCK
XDS_DCA_TDI: U4.5(COM2) ; port XDS_DCA_TDI
XDS_DCA_TDO_SOP0: R203.1 U4.7(COM3) ; port XDS_DCA_TDO_SOP0
XDS_DCA_TMS: U4.10(COM4) ; port XDS_DCA_TMS
XDS_RS232_RX: U12.1(NO2) ; port XDS_RS232_RX
XDS_RS232_TX: U12.13(NO1) ; port XDS_RS232_TX
XDS_SOP0: R43.1 ; port XDS_SOP0
XDS_SOP1: R67.1 ; port XDS_SOP1
XDS_TCK: U4.1(NO1) ; port XDS_TCK
XDS_TDI: U4.4(NO2) ; port XDS_TDI
XDS_TDO: U4.8(NO3) ; port XDS_TDO
XDS_TMS: U4.11(NO4) ; port XDS_TMS
XDS_UARTA_RX: R127.2 U12.7(NC3) ; port XDS_UARTA_RX
XDS_UARTA_RX_CAN_RX: R127.1 U12.6(COM3) ; port XDS_UARTA_RX_CAN_RX
XDS_UARTA_TX: R128.2 U12.11(NC4) ; port XDS_UARTA_TX
XDS_UARTA_TX_CAN_TX: R128.1 U12.10(COM4) ; port XDS_UARTA_TX_CAN_TX
NetR6_2: R6.2 U4.13(~{EN})
NetR13_2: R13.2 R203.2 SW1.2(C)
NetR16_2: R16.2 R206.2 R207.1 R208.2
NetR33_2: R33.2 U24.13(~{EN})
NetR70_1: R70.1 S4.8(B1)

Not connected (* = marked no-connect by the designer): S4 4(A4)*

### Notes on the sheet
- CONTROL TABLE
- S4.1
- CAN PHY : Stand-by Mode Disable
- Switch Position OFF
- CAN PHY : Stand-by Mode Enable
- Switch Position ON
- S4.2
- S4.3
- LIN PHY : Enable
- FTDI SPI
- LIN PHY : Disable
- DCA SPI
- SOP CONFIGURATION
- SWITCH POSITION
- MUX TABLE
- SOP_MODE1
- SOP Mode
- Device management mode / QSPI Flashing mode
- PMIC_CLK_OUT, TDO
- Combination
- 0 0
- S1.1(SOP1)
- OFF
- 2--3
- SW1(SOP0)
- S1.3
- S1.2
- LVDS
- XDS_JTAG
- LIN_RX, XDS_UARTA/CAN, NERROR_LED,
- WATCH_DOG_TP, RTC_CLK_IN_TP,
- DCA_JTAG
- SOP_MODE2
- SOP_MODE4
- Application mode / Functional mode
- Debug mode / mmWave studio connectivity mode
- 0 1
- 1 1
- ON
- 2--1
- S1.4
- S1.5
- XDS_RS232
- CAN
- HOST_CLK_TP
- DCA_RS232
- XDS_UARTA
- S1.6
- I2C, REG_MODE, LED_SW_GPIO
- SPI
- DCA_FTDI_HOST_INTR_1 is the SPI_BUSY signal

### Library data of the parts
C2 C40 C41 = CMP-0078241-1: CAP, CERM, 0.1 µF, 10 V,+/- 10%, X7R, 0402; Manufacturer: Kemet; TaMin_C: -55°C; Polarized: N; SizeAreaWB_mm2: 3; U/M: EA; Value: 0.1uF; TaMax_C: 125°C; SizeZ_mm: 0.6; SizeX_mm: 1; SizeY_mm: 0.5; Value2: 10V; CompType: Capacitor; Cap_F: 100nF; AEC Category: Q200
R5 R7 R8 R23 R27 R152 R203 R206 = CMP-0025958-3: as R2 on sheet PROC177B_Temp_Current_sensors_EPROM
R6 R33 = CMP-0026938-5: RES, 4.7 k, 5%, 0.063 W, AEC-Q200 Grade 0, 0402; Manufacturer: Vishay-Dale; Power_W: 63mW; TempCo: 200 ppm/C; Value_Code: 4k70; Value: 4.7k; EIA_Code: E24; SizeX_mm: 1; SizeY_mm: 0.5; SizeZ_mm: 0.6; Value2: 0.063W; AEC Qualified: Y; VDC_V: 50V; AEC Category: Q200; AEC Grade: 0
R13 R16 = CMP-0026542-2: RES, 750, 1%, 0.063 W, AEC-Q200 Grade 0, 0402; Manufacturer: Vishay-Dale; Power_W: 63mW; TempCo: 100 ppm/C; Value_Code: 750R; Value: 750; EIA_Code: E96; SizeX_mm: 1; SizeY_mm: 0.5; SizeZ_mm: 0.6; Value2: 0.063W; AEC Qualified: Y; VDC_V: 50V; AEC Grade: 0; AEC Category: Q200
R15 R43 R67 = CMP-0002710-1: 0 Ohms Jumper Chip Resistor 0402 (1005 Metric) Automotive AEC-Q200 Thick Film; Manufacturer: Panasonic; SizeZ_mm: 0.4mm; AEC Qualified: Yes; AEC Grade: Grade 0; Power: 100mW
R70 = CMP-0026071-3: RES, 1.00 k, 1%, 0.063 W, AEC-Q200 Grade 0, 0402; Manufacturer: Vishay-Dale; Power_W: 63mW; TempCo: 100 ppm/C; Value_Code: 1k00; Value: 1.00k; EIA_Code: E96; Res_ohm: 1k; SizeX_mm: 1; SizeY_mm: 0.5; SizeZ_mm: 0.6; Value2: 0.063W; AEC Qualified: Y; VDC_V: 50V; AEC Category: Q200; AEC Grade: 0
R127 R128 = CMP-0002710-1: as R25 on sheet PROC177B_Temp_Current_sensors_EPROM
R204 R207 = CMP-0026557-2: RES, 7.87 k, 1%, 0.063 W, AEC-Q200 Grade 0, 0402; Manufacturer: Vishay-Dale; Power_W: 63mW; TempCo: 100 ppm/C; Value_Code: 7k87; Value: 7.87k; EIA_Code: E96; SizeX_mm: 1; SizeY_mm: 0.5; SizeZ_mm: 0.6; Value2: 0.063W; AEC Qualified: Y; VDC_V: 50V; AEC Grade: 0; AEC Category: Q200
R205 R208 = CMP-0026574-2: RES, 82.5 k, 1%, 0.063 W, AEC-Q200 Grade 0, 0402; Manufacturer: Vishay-Dale; Power_W: 63mW; TempCo: 100 ppm/C; Value_Code: 82k5; Value: 82.5k; EIA_Code: E96; SizeX_mm: 1; SizeY_mm: 0.5; SizeZ_mm: 0.6; Value2: 0.063W; AEC Qualified: Y; VDC_V: 50V; AEC Grade: 0; AEC Category: Q200
S1 = CMP-0002304-1: Switch, SPST, Slide, Off-On, 6 Pos, 0.025A, 24V, SMD; Manufacturer: CTS Electrocomponents; CurrentRating_mA: 25A; PositionCount: 6; SizeX_mm: 8.44; SizeY_mm: 8.79; SizeZ_mm: 2.65; SizeArea_mm2: 74.1876; SizeAreaWB_mm2: 112.6476
S4 = CMP-0002128-3: Switch, Slide, SPST 4 poles, SMT; Manufacturer: CTS Electrocomponents; CurrentRating_mA: 25A; PositionCount: 4; VDC_V: 24V; SwitchFunction: Off-On
SW1 = CMP-0096333-1: Slide Switch SPDT Surface Mount, Right Angle; Manufacturer: C&K Switches; Coil Resistance_ohm: 80mΩ; SizeZ_mm: 1.5mm; AEC Qualified: No; VDC_V: 12V; Contact Current Rating: 100mA; Electromechanical Life: 10000Cycles
TP1 = CMP-0078143-3: TEST POINT.  No entry in BOM.
U4 U24 = CMP-0067415-1: 10-Ohm Quad SPDT Analog Switch, RSV0016A (UQFN-16); Alternate Manufacturer: Texas Instruments; SizeAreaWB_mm2: 10.08; U/M: EA; SizeZ_mm: 0.55; SizeX_mm: 1.8; SizeY_mm: 2.6; SizeArea_mm2: 4.68; CompType: IC
U12 = CMP-0067412-1: 0.45-Ohm Quad SPDT Analog Switch Quad-Channel 2:1 Multiplexer/Demultiplexer with Two Controls, PW0016A (TSSOP-16); Alternate Manufacturer: Texas Instruments; SizeAreaWB_mm2: 58.8; U/M: EA; SizeZ_mm: 1.2; SizeX_mm: 6.4; SizeY_mm: 5.0; SizeArea_mm2: 32.0; CompType: IC

## Sheet PROC177B_Analog_MUX_SPI.SchDoc: Analog Mux SPI
size 431 x 279 mm; Date: Not shown in title block; ApprovedBy: Not shown in title block; CheckedBy: Not shown in title block; Author: Not shown in title block; CompanyName: Not shown in title block; DrawnBy: Mistral; Engineer: Not shown in title block; Organization: Not shown in title block; Address1: Not shown in title block; Address2: Not shown in title block; Address3: Not shown in title block; Address4: Not shown in title block; DocumentNumber: 3; Revision: Use project parameter SCH_Rev; SheetNumber: 10; SheetTotal: 17; PageSetup: Record=PageOptions¦CenterHorizontal=True¦CenterVertical=True¦PrintScale=1.00¦XCorrection=1.00¦YCorrection=1.00¦PrintKind=0¦BorderSize=5000000¦LeftOffset=0¦BottomOffset=0¦Orientation=2¦PaperLength=1000¦PaperWidth=1000¦Scale=100¦PaperSource=15¦PrintQuality=600¦MediaType=1¦DitherType=10¦PaperKind=Letter¦PrintScaleMode=1
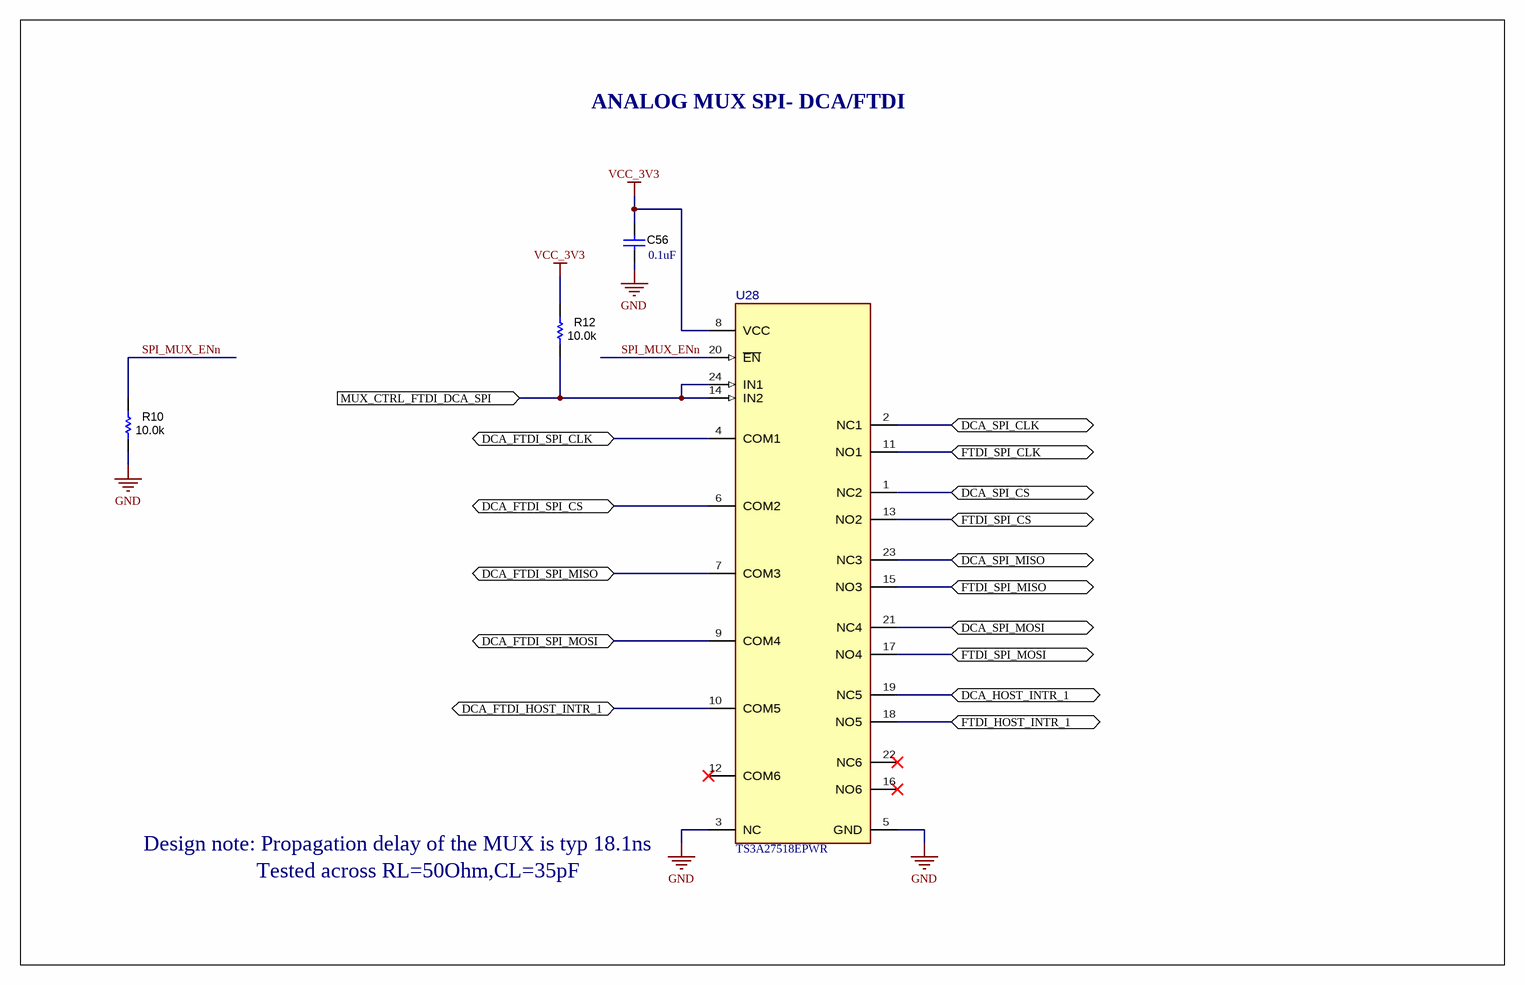
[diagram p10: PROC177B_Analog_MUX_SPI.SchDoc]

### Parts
C56  ValueDisplayed: 0.1uF  [0402]  (hidden comment: GCM155R71H104KE02D)
R10  ValueDisplayed: 10.0k  [0402L]  (hidden comment: CRCW040210K0FKED)
R12  ValueDisplayed: 10.0k  [0402L]  (hidden comment: CRCW040210K0FKED)
U28  TS3A27518EPWR  [PW0024A-MFG]

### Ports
DCA_FTDI_HOST_INTR_1 (bidir), DCA_FTDI_SPI_CLK (bidir), DCA_FTDI_SPI_CS (bidir), DCA_FTDI_SPI_MISO (bidir), DCA_FTDI_SPI_MOSI (bidir), DCA_HOST_INTR_1 (bidir), DCA_SPI_CLK (bidir), DCA_SPI_CS (bidir), DCA_SPI_MISO (bidir), DCA_SPI_MOSI (bidir), FTDI_HOST_INTR_1 (bidir), FTDI_SPI_CLK (bidir), FTDI_SPI_CS (bidir), FTDI_SPI_MISO (bidir), FTDI_SPI_MOSI (bidir), MUX_CTRL_FTDI_DCA_SPI (in)

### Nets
GND: C56.2 R10.2 U28.3(NC) U28.5(GND)
VCC_3V3: C56.1 R12.1 U28.8(VCC)
DCA_FTDI_HOST_INTR_1: U28.10(COM5) ; port DCA_FTDI_HOST_INTR_1
DCA_FTDI_SPI_CLK: U28.4(COM1) ; port DCA_FTDI_SPI_CLK
DCA_FTDI_SPI_CS: U28.6(COM2) ; port DCA_FTDI_SPI_CS
DCA_FTDI_SPI_MISO: U28.7(COM3) ; port DCA_FTDI_SPI_MISO
DCA_FTDI_SPI_MOSI: U28.9(COM4) ; port DCA_FTDI_SPI_MOSI
DCA_HOST_INTR_1: U28.19(NC5) ; port DCA_HOST_INTR_1
DCA_SPI_CLK: U28.2(NC1) ; port DCA_SPI_CLK
DCA_SPI_CS: U28.1(NC2) ; port DCA_SPI_CS
DCA_SPI_MISO: U28.23(NC3) ; port DCA_SPI_MISO
DCA_SPI_MOSI: U28.21(NC4) ; port DCA_SPI_MOSI
FTDI_HOST_INTR_1: U28.18(NO5) ; port FTDI_HOST_INTR_1
FTDI_SPI_CLK: U28.11(NO1) ; port FTDI_SPI_CLK
FTDI_SPI_CS: U28.13(NO2) ; port FTDI_SPI_CS
FTDI_SPI_MISO: U28.15(NO3) ; port FTDI_SPI_MISO
FTDI_SPI_MOSI: U28.17(NO4) ; port FTDI_SPI_MOSI
MUX_CTRL_FTDI_DCA_SPI: R12.2 U28.14(IN2) U28.24(IN1) ; port MUX_CTRL_FTDI_DCA_SPI
SPI_MUX_ENn: R10.1 U28.20(~{EN})

Not connected (* = marked no-connect by the designer): U28 12(COM6)* 16(NO6)* 22(NC6)*

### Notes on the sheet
- ANALOG MUX SPI- DCA/FTDI
- (near U28) Design note: Propagation delay of the MUX is typ 18.1ns
- Tested across RL=50Ohm,CL=35pF

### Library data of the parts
C56 = CMP-0006356-2: as C36 on sheet PROC177B_Temp_Current_sensors_EPROM
R10 R12 = CMP-0025958-3: as R2 on sheet PROC177B_Temp_Current_sensors_EPROM
U28 = CMP-0092155-1: as U15 on sheet PROC177B_LVDS_Driver

## Sheet PROC177B_XDS110_Interface.SchDoc: XDS110_INTERFACE
size 431 x 279 mm; Date: Not shown in title block; ApprovedBy: Not shown in title block; CheckedBy: Not shown in title block; Author: Not shown in title block; CompanyName: Not shown in title block; DrawnBy: Mistral; Engineer: Not shown in title block; Organization: Not shown in title block; Address1: Not shown in title block; Address2: Not shown in title block; Address3: Not shown in title block; Address4: Not shown in title block; DocumentNumber: 12; Revision: Use project parameter SCH_Rev; SheetNumber: 12; SheetTotal: 17; PageSetup: Record=PageOptions¦CenterHorizontal=True¦CenterVertical=True¦PrintScale=1.00¦XCorrection=1.00¦YCorrection=1.00¦PrintKind=0¦BorderSize=5000000¦LeftOffset=0¦BottomOffset=0¦Orientation=2¦PaperLength=1000¦PaperWidth=1000¦Scale=100¦PaperSource=15¦PrintQuality=600¦MediaType=1¦DitherType=10¦PaperKind=Letter¦PrintScaleMode=1
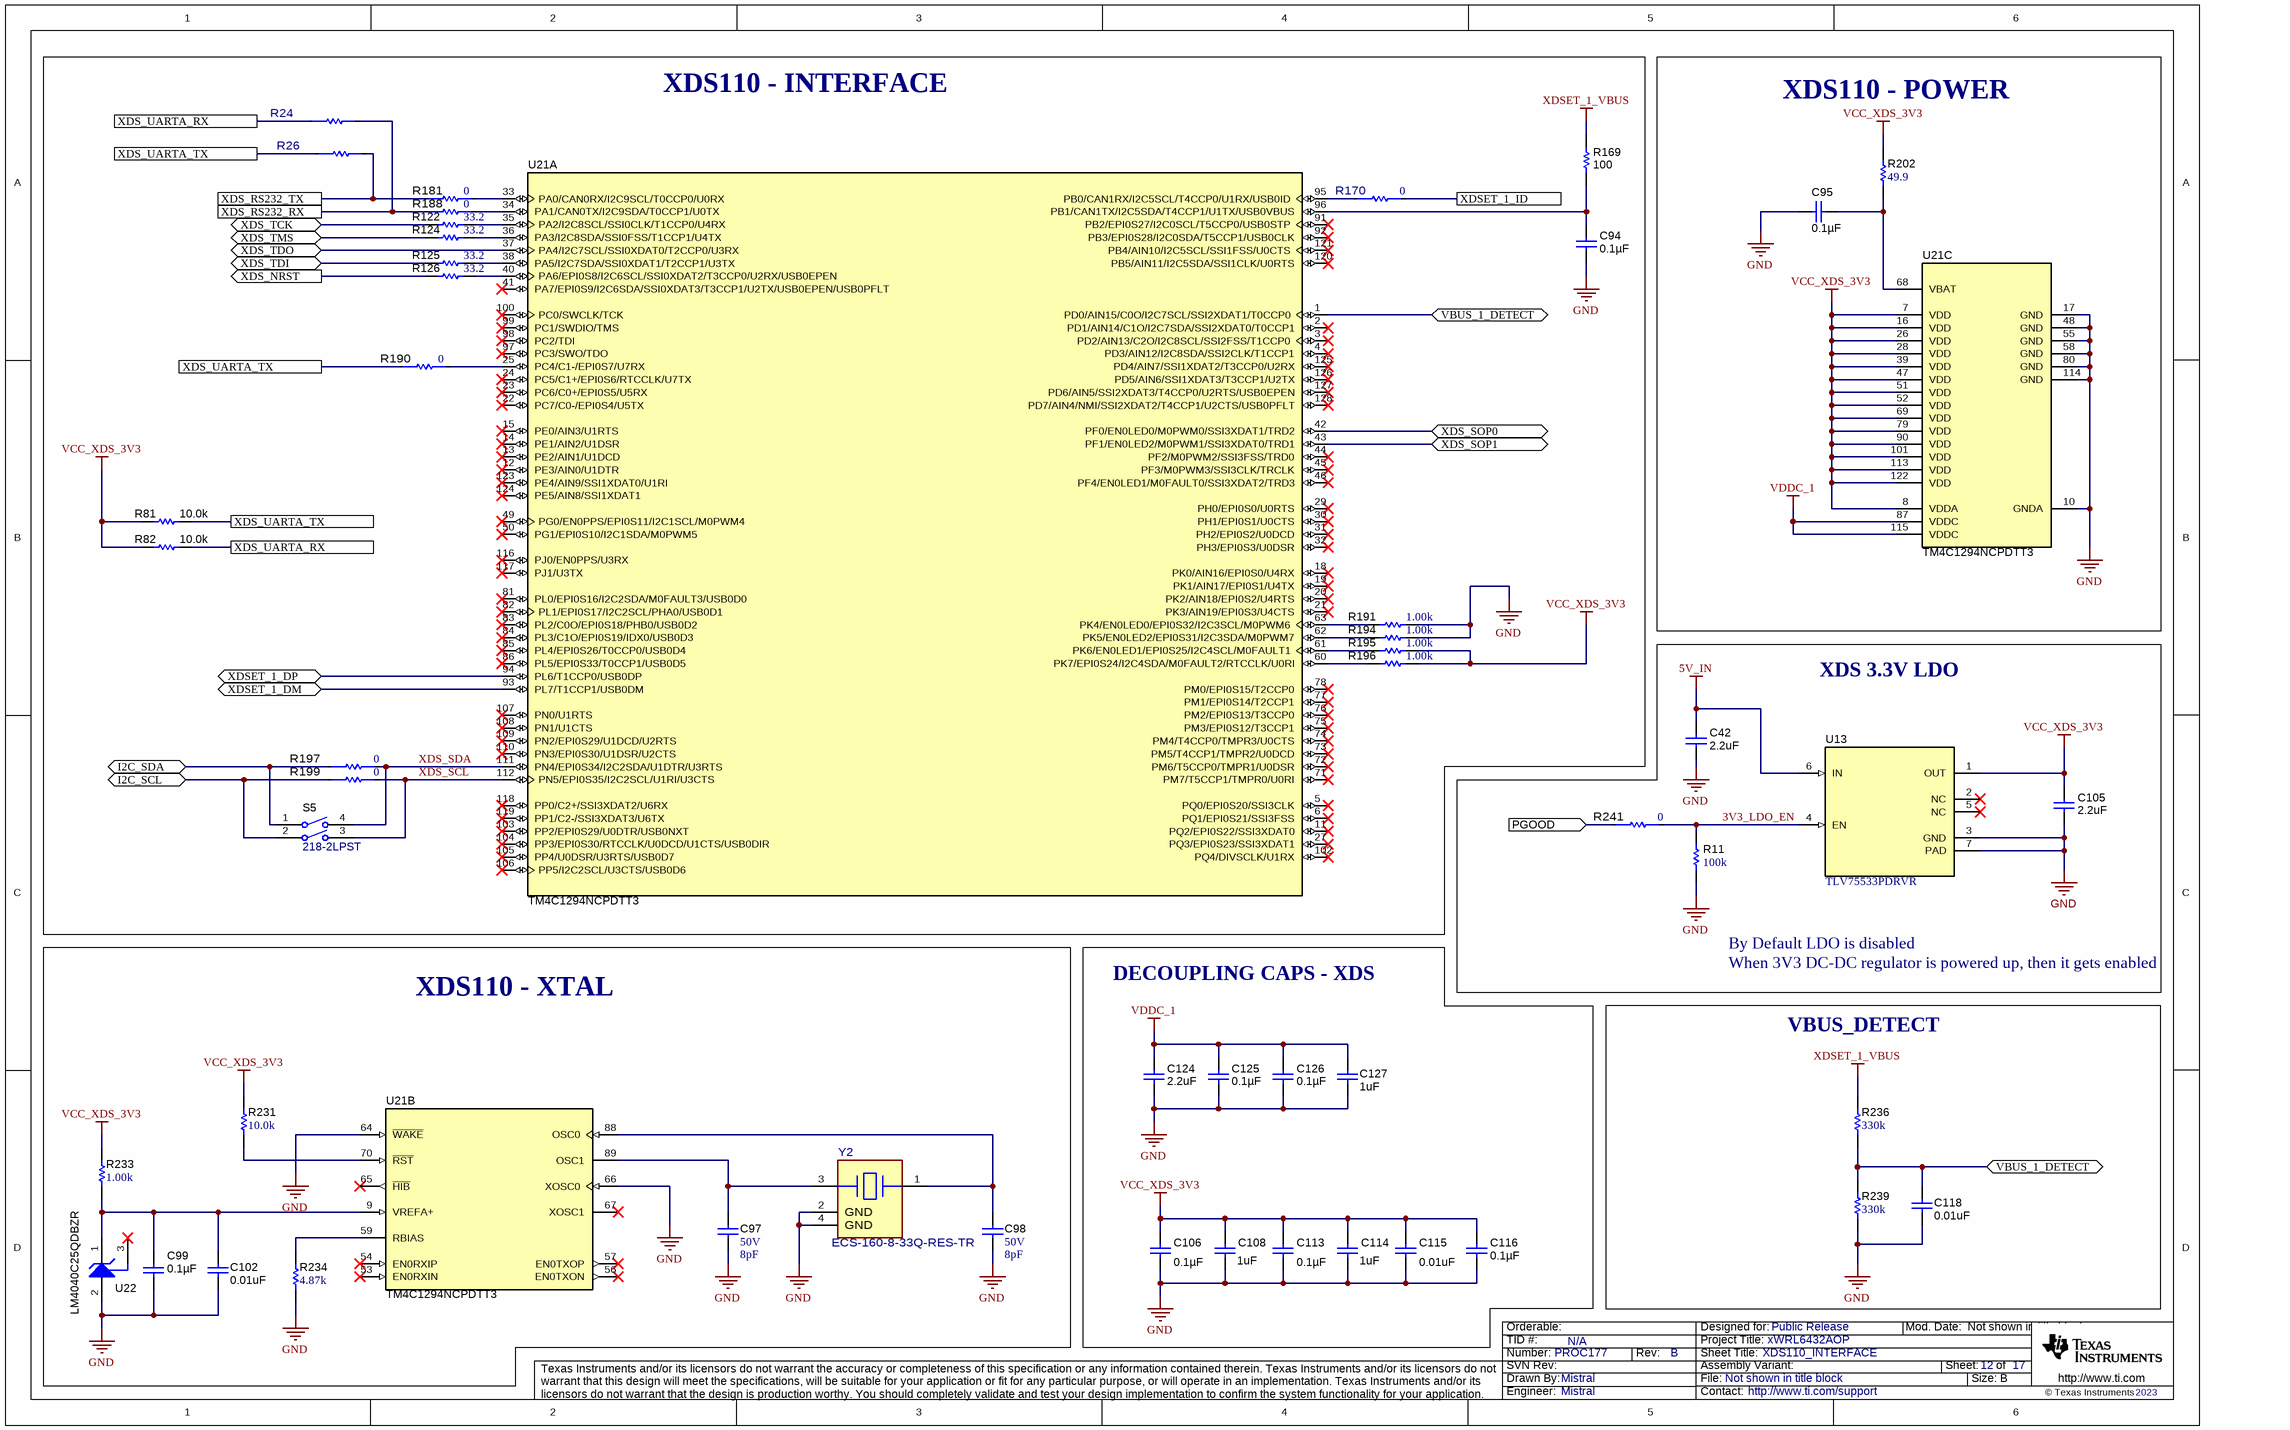
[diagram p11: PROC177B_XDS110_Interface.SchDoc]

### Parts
C42  ValueDisplayed: 2.2uF  [0402_065L]  (hidden comment: C1005X7S1A225K050BC)
C94  ValueDisplayed: 0.1µF  [0402]  (hidden comment: C0402C104K8RACTU)
C95  ValueDisplayed: 0.1µF  [0402]  (hidden comment: C0402C104K8RACTU)
C97  VDC_V: 50V  ValueDisplayed: 8pF  [0402L]  (hidden comment: CC0402DRNPO9BN8R0)
C98  VDC_V: 50V  ValueDisplayed: 8pF  [0402L]  (hidden comment: CC0402DRNPO9BN8R0)
C99  ValueDisplayed: 0.1µF  [0402]  (hidden comment: C0402C104K8RACTU)
C102  ValueDisplayed: 0.01uF  [0402L]  (hidden comment: GCM155R71E103KA37D)
C105  ValueDisplayed: 2.2uF  [0402_065L]  (hidden comment: C1005X7S1A225K050BC)
C106  ValueDisplayed: 0.1µF  [0402]  (hidden comment: C0402C104K8RACTU)
C108  ValueDisplayed: 1uF  [0402L]  (hidden comment: GRT155C81A105KE01D)
C113  ValueDisplayed: 0.1µF  [0402]  (hidden comment: C0402C104K8RACTU)
C114  ValueDisplayed: 1uF  [0402L]  (hidden comment: GRT155C81A105KE01D)
C115  ValueDisplayed: 0.01uF  [0402L]  (hidden comment: GCM155R71E103KA37D)
C116  ValueDisplayed: 0.1µF  [0402]  (hidden comment: C0402C104K8RACTU)
C118  ValueDisplayed: 0.01uF  [0402L]  (hidden comment: GCM155R71E103KA37D)
C124  ValueDisplayed: 2.2uF  [0402_065L]  (hidden comment: C1005X7S1A225K050BC)
C125  ValueDisplayed: 0.1µF  [0402]  (hidden comment: C0402C104K8RACTU)
C126  ValueDisplayed: 0.1µF  [0402]  (hidden comment: C0402C104K8RACTU)
C127  ValueDisplayed: 1uF  [0402L]  (hidden comment: GRT155C81A105KE01D)
R11  ValueDisplayed: 100k  [0402]  (hidden comment: CRCW0402100KFKED)
R24  ERJ-2GE0R00X  [FP-ERJ-2GE0R00X_0402-MFG]  (value not drawn)
R26  ERJ-2GE0R00X  [FP-ERJ-2GE0R00X_0402-MFG]  (value not drawn)
R81  ValueDisplayed: 10.0k  [0402L]  (hidden comment: CRCW040210K0FKED)
R82  ValueDisplayed: 10.0k  [0402L]  (hidden comment: CRCW040210K0FKED)
R122  ValueDisplayed: 33.2  [0402]  (hidden comment: CRCW040233R2FKED)
R124  ValueDisplayed: 33.2  [0402]  (hidden comment: CRCW040233R2FKED)
R125  ValueDisplayed: 33.2  [0402]  (hidden comment: CRCW040233R2FKED)
R126  ValueDisplayed: 33.2  [0402]  (hidden comment: CRCW040233R2FKED)
R169  ValueDisplayed: 100  [0402L]  (hidden comment: ERJ-2GEJ101X)
R170  value 0  [FP-ERJ-2GE0R00X_0402-MFG]  (hidden comment: ERJ-2GE0R00X)
R181  value 0  [FP-ERJ-2GE0R00X_0402-MFG]  (hidden comment: ERJ-2GE0R00X)
R188  value 0  [FP-ERJ-2GE0R00X_0402-MFG]  (hidden comment: ERJ-2GE0R00X)
R190  value 0  [FP-ERJ-2GE0R00X_0402-MFG]  (hidden comment: ERJ-2GE0R00X)
R191  ValueDisplayed: 1.00k  [0402]  (hidden comment: CRCW04021K00FKED)
R194  ValueDisplayed: 1.00k  [0402]  (hidden comment: CRCW04021K00FKED)
R195  ValueDisplayed: 1.00k  [0402]  (hidden comment: CRCW04021K00FKED)
R196  ValueDisplayed: 1.00k  [0402]  (hidden comment: CRCW04021K00FKED)
R197  value 0  [FP-ERJ-2GE0R00X_0402-MFG]  (hidden comment: ERJ-2GE0R00X)
R199  value 0  [FP-ERJ-2GE0R00X_0402-MFG]  (hidden comment: ERJ-2GE0R00X)
R202  ValueDisplayed: 49.9  [0402L]  (hidden comment: CRCW040249R9FKED)
R231  ValueDisplayed: 10.0k  [0402L]  (hidden comment: CRCW040210K0FKED)
R233  ValueDisplayed: 1.00k  [0402]  (hidden comment: CRCW04021K00FKED)
R234  ValueDisplayed: 4.87k  [0402L]  (hidden comment: CRCW04024K87FKED)
R236  ValueDisplayed: 330k  [0402L]  (hidden comment: CRCW0402330KFKED)
R239  ValueDisplayed: 330k  [0402L]  (hidden comment: CRCW0402330KFKED)
R241  value 0  [FP-ERJ-2GE0R00X_0402-MFG]  (hidden comment: ERJ-2GE0R00X)
S5  218-2LPST  [SW_218-2LP]
U13  TLV75533PDRVR  [DRV0006A]
U21  TM4C1294NCPDTT3  [PDT0128A]  (parts A,B,C of 3)
U22  LM4040C25QDBZR  [DBZ0003A_N]
Y2  ECS-160-8-33Q-RES-TR  [FP-ECS-160-8-33Q-RES-TR_SMT4_3MM2_2MM5-MFG]

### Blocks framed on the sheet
XDS110 - INTERFACE: C94 R24 R26 R81 R82 R122 R124-R126 R169 R170 R181 R188 R190 R191 R194-R197 R199 S5 U21
XDS110 - POWER: C95 R202 U21
XDS 3.3V LDO: C42 C105 R11 R241 U13
XDS110 - XTAL: C97-C99 C102 R231 R233 R234 U21 U22 Y2
DECOUPLING CAPS - XDS: C106 C108 C113-C116 C124-C127
VBUS_DETECT: C118 R236 R239

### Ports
I2C_SCL (bidir), I2C_SDA (bidir), PGOOD (in), VBUS_1_DETECT (bidir), XDS_NRST (out), XDS_RS232_RX, XDS_RS232_TX, XDS_SOP0 (bidir), XDS_SOP1 (bidir), XDS_TCK (bidir), XDS_TDI (bidir), XDS_TDO (bidir), XDS_TMS (bidir), XDS_UARTA_RX, XDS_UARTA_TX, XDSET_1_DM (bidir), XDSET_1_DP (bidir), XDSET_1_ID

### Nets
5V_IN: C42.1 U13.6(IN)
GND: C42.2 C94.2 C95.1 C97.1 C98.1 C99.1 C102.1 C105.1 C106.1 C108.2 C113.1 C114.2 C115.2 C116.1 C118.1 C124.1 C125.1 C126.1 C127.2 R11.1 R191.2 R194.2 R234.1 R239.1 U13.3(GND) U13.7(PAD) U21.10(GNDA) U21.17(GND) U21.48(GND) U21.55(GND) U21.58(GND) U21.64(~{WAKE}) U21.66(XOSC0) U21.80(GND) U21.114(GND) U22.2(ANODE) Y2.2(GND) Y2.4(GND)
VCC_XDS_3V3: C105.2 C106.2 C108.1 C113.2 C114.1 C115.1 C116.2 R81.2 R82.2 R195.2 R196.2 R202.1 R231.2 R233.2 U13.1(OUT) U21.7(VDD) U21.8(VDDA) U21.16(VDD) U21.26(VDD) U21.28(VDD) U21.39(VDD) U21.47(VDD) U21.51(VDD) U21.52(VDD) U21.69(VDD) U21.79(VDD) U21.90(VDD) U21.101(VDD) U21.113(VDD) U21.122(VDD)
VDDC_1: C124.2 C125.2 C126.2 C127.1 U21.87(VDDC) U21.115(VDDC)
XDSET_1_VBUS: R169.2 R236.2
3V3_LDO_EN: R11.2 R241.2 U13.4(EN)
I2C_SCL: R199.1 S5.2 ; port I2C_SCL
I2C_SDA: R197.1 S5.1 ; port I2C_SDA
PGOOD: R241.1 ; port PGOOD
VBUS_1_DETECT: C118.2 R236.1 R239.2 U21.1(PD0/AIN15/C0O/I2C7SCL/SSI2XDAT1/T0CCP0) ; port VBUS_1_DETECT
XDS_NRST: R126.2 ; port XDS_NRST
XDS_RS232_RX: R24.2 R188.1 ; port XDS_RS232_RX
XDS_RS232_TX: R26.2 R181.1 ; port XDS_RS232_TX
XDS_SCL: R199.2 S5.3 U21.112(PN5/EPI0S35/I2C2SCL/U1RI/U3CTS)
XDS_SDA: R197.2 S5.4 U21.111(PN4/EPI0S34/I2C2SDA/U1DTR/U3RTS)
XDS_SOP0: U21.42(PF0/EN0LED0/M0PWM0/SSI3XDAT1/TRD2) ; port XDS_SOP0
XDS_SOP1: U21.43(PF1/EN0LED2/M0PWM1/SSI3XDAT0/TRD1) ; port XDS_SOP1
XDS_TCK: R122.2 ; port XDS_TCK
XDS_TDI: R125.2 ; port XDS_TDI
XDS_TDO: U21.37(PA4/I2C7SCL/SSI0XDAT0/T2CCP0/U3RX) ; port XDS_TDO
XDS_TMS: R124.2 ; port XDS_TMS
XDS_UARTA_RX: R24.1 R82.1 ; port XDS_UARTA_RX
XDS_UARTA_TX: R26.1 R81.1 R190.1 ; port XDS_UARTA_TX
XDSET_1_DM: U21.93(PL7/T1CCP1/USB0DM) ; port XDSET_1_DM
XDSET_1_DP: U21.94(PL6/T1CCP0/USB0DP) ; port XDSET_1_DP
XDSET_1_ID: R170.2 ; port XDSET_1_ID
NetC94_1: C94.1 R169.1 U21.96(PB1/CAN1TX/I2C5SDA/T4CCP1/U1TX/USB0VBUS)
NetC95_2: C95.2 R202.2 U21.68(VBAT)
NetC97_2: C97.2 U21.89(OSC1) Y2.3(OUT/IN)
NetC98_2: C98.2 U21.88(OSC0) Y2.1(IN/OUT)
NetC99_2: C99.2 C102.2 R233.1 U21.9(VREFA+) U22.1(CATHODE)
NetR122_1: R122.1 U21.35(PA2/I2C8SCL/SSI0CLK/T1CCP0/U4RX)
NetR124_1: R124.1 U21.36(PA3/I2C8SDA/SSI0FSS/T1CCP1/U4TX)
NetR125_1: R125.1 U21.38(PA5/I2C7SDA/SSI0XDAT1/T2CCP1/U3TX)
NetR126_1: R126.1 U21.40(PA6/EPI0S8/I2C6SCL/SSI0XDAT2/T3CCP0/U2RX/USB0EPEN)
NetR170_1: R170.1 U21.95(PB0/CAN1RX/I2C5SCL/T4CCP0/U1RX/USB0ID)
NetR181_2: R181.2 U21.33(PA0/CAN0RX/I2C9SCL/T0CCP0/U0RX)
NetR188_2: R188.2 U21.34(PA1/CAN0TX/I2C9SDA/T0CCP1/U0TX)
NetR190_2: R190.2 U21.25(PC4/C1-/EPI0S7/U7RX)
NetR191_1: R191.1 U21.63(PK4/EN0LED0/EPI0S32/I2C3SCL/M0PWM6)
NetR194_1: R194.1 U21.62(PK5/EN0LED2/EPI0S31/I2C3SDA/M0PWM7)
NetR195_1: R195.1 U21.61(PK6/EN0LED1/EPI0S25/I2C4SCL/M0FAULT1)
NetR196_1: R196.1 U21.60(PK7/EPI0S24/I2C4SDA/M0FAULT2/RTCCLK/U0RI)
NetR231_1: R231.1 U21.70(~{RST})
NetR234_2: R234.2 U21.59(RBIAS)

Not connected (* = marked no-connect by the designer): U13 2(NC)* 5(NC)*; U21 2(PD1/AIN14/C1O/I2C7SDA/SSI2XDAT0/T0CCP1)* 3(PD2/AIN13/C2O/I2C8SCL/SSI2FSS/T1CCP0)* 4(PD3/AIN12/I2C8SDA/SSI2CLK/T1CCP1)* 5(PQ0/EPI0S20/SSI3CLK)* 6(PQ1/EPI0S21/SSI3FSS)* 11(PQ2/EPI0S22/SSI3XDAT0)* 12(PE3/AIN0/U1DTR)* 13(PE2/AIN1/U1DCD)* 14(PE1/AIN2/U1DSR)* 15(PE0/AIN3/U1RTS)* 18(PK0/AIN16/EPI0S0/U4RX)* 19(PK1/AIN17/EPI0S1/U4TX)* 20(PK2/AIN18/EPI0S2/U4RTS)* 21(PK3/AIN19/EPI0S3/U4CTS)* 22(PC7/C0-/EPI0S4/U5TX)* 23(PC6/C0+/EPI0S5/U5RX)* 24(PC5/C1+/EPI0S6/RTCCLK/U7TX)* 27(PQ3/EPI0S23/SSI3XDAT1)* 29(PH0/EPI0S0/U0RTS)* 30(PH1/EPI0S1/U0CTS)* 31(PH2/EPI0S2/U0DCD)* 32(PH3/EPI0S3/U0DSR)* 41(PA7/EPI0S9/I2C6SDA/SSI0XDAT3/T3CCP1/U2TX/USB0EPEN/USB0PFLT)* 44(PF2/M0PWM2/SSI3FSS/TRD0)* 45(PF3/M0PWM3/SSI3CLK/TRCLK)* 46(PF4/EN0LED1/M0FAULT0/SSI3XDAT2/TRD3)* 49(PG0/EN0PPS/EPI0S11/I2C1SCL/M0PWM4)* 50(PG1/EPI0S10/I2C1SDA/M0PWM5)* 53(EN0RXIN)* 54(EN0RXIP)* 56(EN0TXON)* 57(EN0TXOP)* 65(~{HIB})* 67(XOSC1)* 71(PM7/T5CCP1/TMPR0/U0RI)* 72(PM6/T5CCP0/TMPR1/U0DSR)* 73(PM5/T4CCP1/TMPR2/U0DCD)* 74(PM4/T4CCP0/TMPR3/U0CTS)* 75(PM3/EPI0S12/T3CCP1)* 76(PM2/EPI0S13/T3CCP0)* 77(PM1/EPI0S14/T2CCP1)* 78(PM0/EPI0S15/T2CCP0)* 81(PL0/EPI0S16/I2C2SDA/M0FAULT3/USB0D0)* 82(PL1/EPI0S17/I2C2SCL/PHA0/USB0D1)* 83(PL2/C0O/EPI0S18/PHB0/USB0D2)* 84(PL3/C1O/EPI0S19/IDX0/USB0D3)* 85(PL4/EPI0S26/T0CCP0/USB0D4)* 86(PL5/EPI0S33/T0CCP1/USB0D5)* 91(PB2/EPI0S27/I2C0SCL/T5CCP0/USB0STP)* 92(PB3/EPI0S28/I2C0SDA/T5CCP1/USB0CLK)* 97(PC3/SWO/TDO)* 98(PC2/TDI)* 99(PC1/SWDIO/TMS)* 100(PC0/SWCLK/TCK)* 102(PQ4/DIVSCLK/U1RX)* 103(PP2/EPI0S29/U0DTR/USB0NXT)* 104(PP3/EPI0S30/RTCCLK/U0DCD/U1CTS/USB0DIR)* 105(PP4/U0DSR/U3RTS/USB0D7)* 106(PP5/I2C2SCL/U3CTS/USB0D6)* 107(PN0/U1RTS)* 108(PN1/U1CTS)* 109(PN2/EPI0S29/U1DCD/U2RTS)* 110(PN3/EPI0S30/U1DSR/U2CTS)* 116(PJ0/EN0PPS/U3RX)* 117(PJ1/U3TX)* 118(PP0/C2+/SSI3XDAT2/U6RX)* 119(PP1/C2-/SSI3XDAT3/U6TX)* 120(PB5/AIN11/I2C5SDA/SSI1CLK/U0RTS)* 121(PB4/AIN10/I2C5SCL/SSI1FSS/U0CTS)* 123(PE4/AIN9/SSI1XDAT0/U1RI)* 124(PE5/AIN8/SSI1XDAT1)* 125(PD4/AIN7/SSI1XDAT2/T3CCP0/U2RX)* 126(PD5/AIN6/SSI1XDAT3/T3CCP1/U2TX)* 127(PD6/AIN5/SSI2XDAT3/T4CCP0/U2RTS/USB0EPEN)* 128(PD7/AIN4/NMI/SSI2XDAT2/T4CCP1/U2CTS/USB0PFLT)*; U22 3(NC)*

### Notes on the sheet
- By Default LDO is disabled
- When 3V3 DC-DC regulator is powered up, then it gets enabled

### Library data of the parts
C42 C105 C124 = CMP-0006302-2: CAP, CERM, 2.2 uF, 10 V, +/- 10%, X7S, 0402; Manufacturer: TDK; TaMin_C: -55°C; ESR_ohm: 5.925m; Polarized: N; SizeAreaWB_mm2: 3; Value1: 0.005925 ohm; U/M: EA; Value: 2.2uF; TaMax_C: 125°C; SizeZ_mm: 0.65; SizeX_mm: 1; SizeY_mm: 0.5; Cap_Case: 0402_065; Value2: 10V; CompType: Capacitor; Cap_F: 2.2µF; IRMS_A: 2.05591A; AEC Category: Q200
C94 C95 C99 C106 C113 C116 C125 C126 = CMP-0078241-1: as C2 on sheet PROC177B_Analog_Mux_SOP_Ctrl
C97 C98 = CMP-0860185-1: CAP, CERM, 8 pF, 50 V,+/- 6.25%, C0G/NP0, 0402; Manufacturer: Yageo; Cap_Case: 0402; Polarized: N; TaMax_C: 125°C; SizeY_mm: 0.5; SizeX_mm: 1; Value: 8pF; AEC Category: Q200; U/M: EA; SizeAreaWB_mm2: 3; TaMin_C: -55°C; SizeZ_mm: 0.6
C102 C115 C118 = CMP-0006352-2: as C88 on sheet PROC177B_LVDS_Driver
C108 C114 C127 = CMP-0006272-2: CAP, CERM, 1 uF, 10 V, +/- 10%, X6S, 0402; Manufacturer: TDK; Polarized: N; Value: 1uF; U/M: EA; Cap_F: 1µF; Value1: Unknown; VDC_V: 16V; TempCo: X5R; TaMin_C: -55°C; TaMax_C: 85°C; Cap_Case: 0402; SizeArea_mm2: 0.5; SizeAreaWB_mm2: 3; SizeX_mm: 1; SizeZ_mm: 0.6; AEC Category: Q200
R11 = CMP-0025950-3: RES, 100 k, 1%, 0.063 W, AEC-Q200 Grade 0, 0402; Manufacturer: Vishay-Dale; Power_W: 63mW; TempCo: 100 ppm/C; Value: 100k; EIA_Code: E96; SizeX_mm: 1; SizeY_mm: 0.5; SizeZ_mm: 0.6; Value2: 0.063W; AEC Qualified: Y; VDC_V: 50V; AEC Category: Q200; AEC Grade: 0
R24 R26 = CMP-0002710-1: as R25 on sheet PROC177B_Temp_Current_sensors_EPROM
R81 R82 R231 = CMP-0025958-3: as R2 on sheet PROC177B_Temp_Current_sensors_EPROM
R122 R124-R126 = CMP-0026299-2: RES, 33.2, 1%, 0.063 W, AEC-Q200 Grade 0, 0402; Manufacturer: Vishay-Dale; Power_W: 63mW; TempCo: 100 ppm/C; Value_Code: 33R2; Value: 33.2; EIA_Code: E96; SizeX_mm: 1; SizeY_mm: 0.5; SizeZ_mm: 0.6; Value2: 0.063W; AEC Qualified: Y; AEC Grade: 0; AEC Category: Q200; VDC_V: 50V
R169 = CMP-0026993-2: RES, 100, 5%, 0.1 W, AEC-Q200 Grade 0, 0402; Manufacturer: Panasonic; Power_W: 100mW; TempCo: 200 ppm/C; Value_Code: 100R; U/M: EA; Value: 100; EIA_Code: E24; SizeX_mm: 1; SizeY_mm: 0.5; SizeZ_mm: 0.6; Value2: 0.1W; AEC Qualified: Y; AEC Grade: 0; AEC Category: Q200
R170 R181 R188 R190 R197 R199 R241 = CMP-0002710-1: as R15 on sheet PROC177B_Analog_Mux_SOP_Ctrl
R191 R194-R196 R233 = CMP-0026071-3: as R70 on sheet PROC177B_Analog_Mux_SOP_Ctrl
R202 = CMP-0026404-2: RES, 49.9, 1%, 0.063 W, AEC-Q200 Grade 0, 0402; Manufacturer: Vishay-Dale; Power_W: 63mW; TempCo: 100 ppm/C; Value_Code: 49R9; Value: 49.9; EIA_Code: E96; SizeX_mm: 1; SizeY_mm: 0.5; SizeZ_mm: 0.6; Value2: 0.063W; AEC Qualified: Y; VDC_V: 50V; AEC Category: Q200; AEC Grade: 0
R234 = CMP-0026413-2: RES, 4.87 k, 1%, 0.063 W, AEC-Q200 Grade 0, 0402; Manufacturer: Vishay-Dale; Power_W: 63mW; TempCo: 100 ppm/C; Value_Code: 4k87; Value: 4.87k; EIA_Code: E96; SizeX_mm: 1; SizeY_mm: 0.5; SizeZ_mm: 0.6; Value2: 0.063W; AEC Qualified: Y; VDC_V: 50V; AEC Category: Q200; AEC Grade: 0
R236 R239 = CMP-0078210-2: RES, 330 k, 1%, 0.063 W, AEC-Q200 Grade 0, 0402; Manufacturer: Vishay-Dale; SizeArea_mm2: 0.5; AEC Qualified: Y; AEC Category: Q200; Value: 330k; SizeZ_mm: 0.6; TempCo: 100 ppm/C; AEC Grade: 0; Power_W: 63mW; VDC_V: 50V; Value2: 0.063W; SizeX_mm: 1
S5 = CMP-0002230-1: Switch, SPST, 2 Pos, 25mA, 24VDC, SMD; Manufacturer: CTS Electrocomponents; CurrentRating_mA: 25A; PositionCount: 2; VDC_V: 24V; SwitchFunction: Off-On
U13 = CMP-0013427-7: 500mA LDO, DRV0006A (WSON-6); Manufacturer: Texas Instruments; SizeX_mm: 2; CompType: IC; SizeZ_mm: 0.8; SizeArea_mm2: 4; SizeAreaWB_mm2: 9; U/M: EA
U21 = CMP-0029856-2: Tiva C Series Microcontroller, 1024 KB Flash, 256 KB SRAM, 12 Bit, 20 Channels, -40 to 105 degC, 128-Pin TQFP (PDT), Green (RoHS & no Sb/Br), Tray; Manufacturer: Texas Instruments; ADC Channels: 20; CPU: ARM Cortex-M4; Flash: 1024 KB; ADC Resolution: 12 Bits; Max Speed: 120 MHz; SRAM: 256 KB; SizeAreaWB_mm2: 324.0; SizeArea_mm2: 256.0; SizeX_mm: 16.0; SizeZ_mm: 1.2; CompType: IC
U22 = CMP-0033001-1: Precision Micropower Shunt Voltage Reference, 0.5% accuracy, 2.5 V, 15 ppm / degC, 15 mA, -40 to 125 degC, 3-pin SOT-23 (DBZ), Green (RoHS & no Sb/Br); Manufacturer: Texas Instruments; Initial Accuracy @ 25/deg C(%): 0.5; Temp Coeff(Typ)(ppm/ degree C): 15; Temp Coeff(Max)(ppm/ degree C): 100; Rating: Catalog; Min Iz for Regulation(uA): 75; VO(V): 2.5
Y2 = CMP-0095014-1: 16 MHz ±15ppm Crystal 8pF 80 Ohms 4-SMD, No Lead; Manufacturer: ECS; Frequency Stability: 50ppm; SizeZ_mm: 0.8mm; Frequency_Fixed: 16MHz; AEC Qualified: Yes; Esr: 80; AEC Grade: Grade 1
